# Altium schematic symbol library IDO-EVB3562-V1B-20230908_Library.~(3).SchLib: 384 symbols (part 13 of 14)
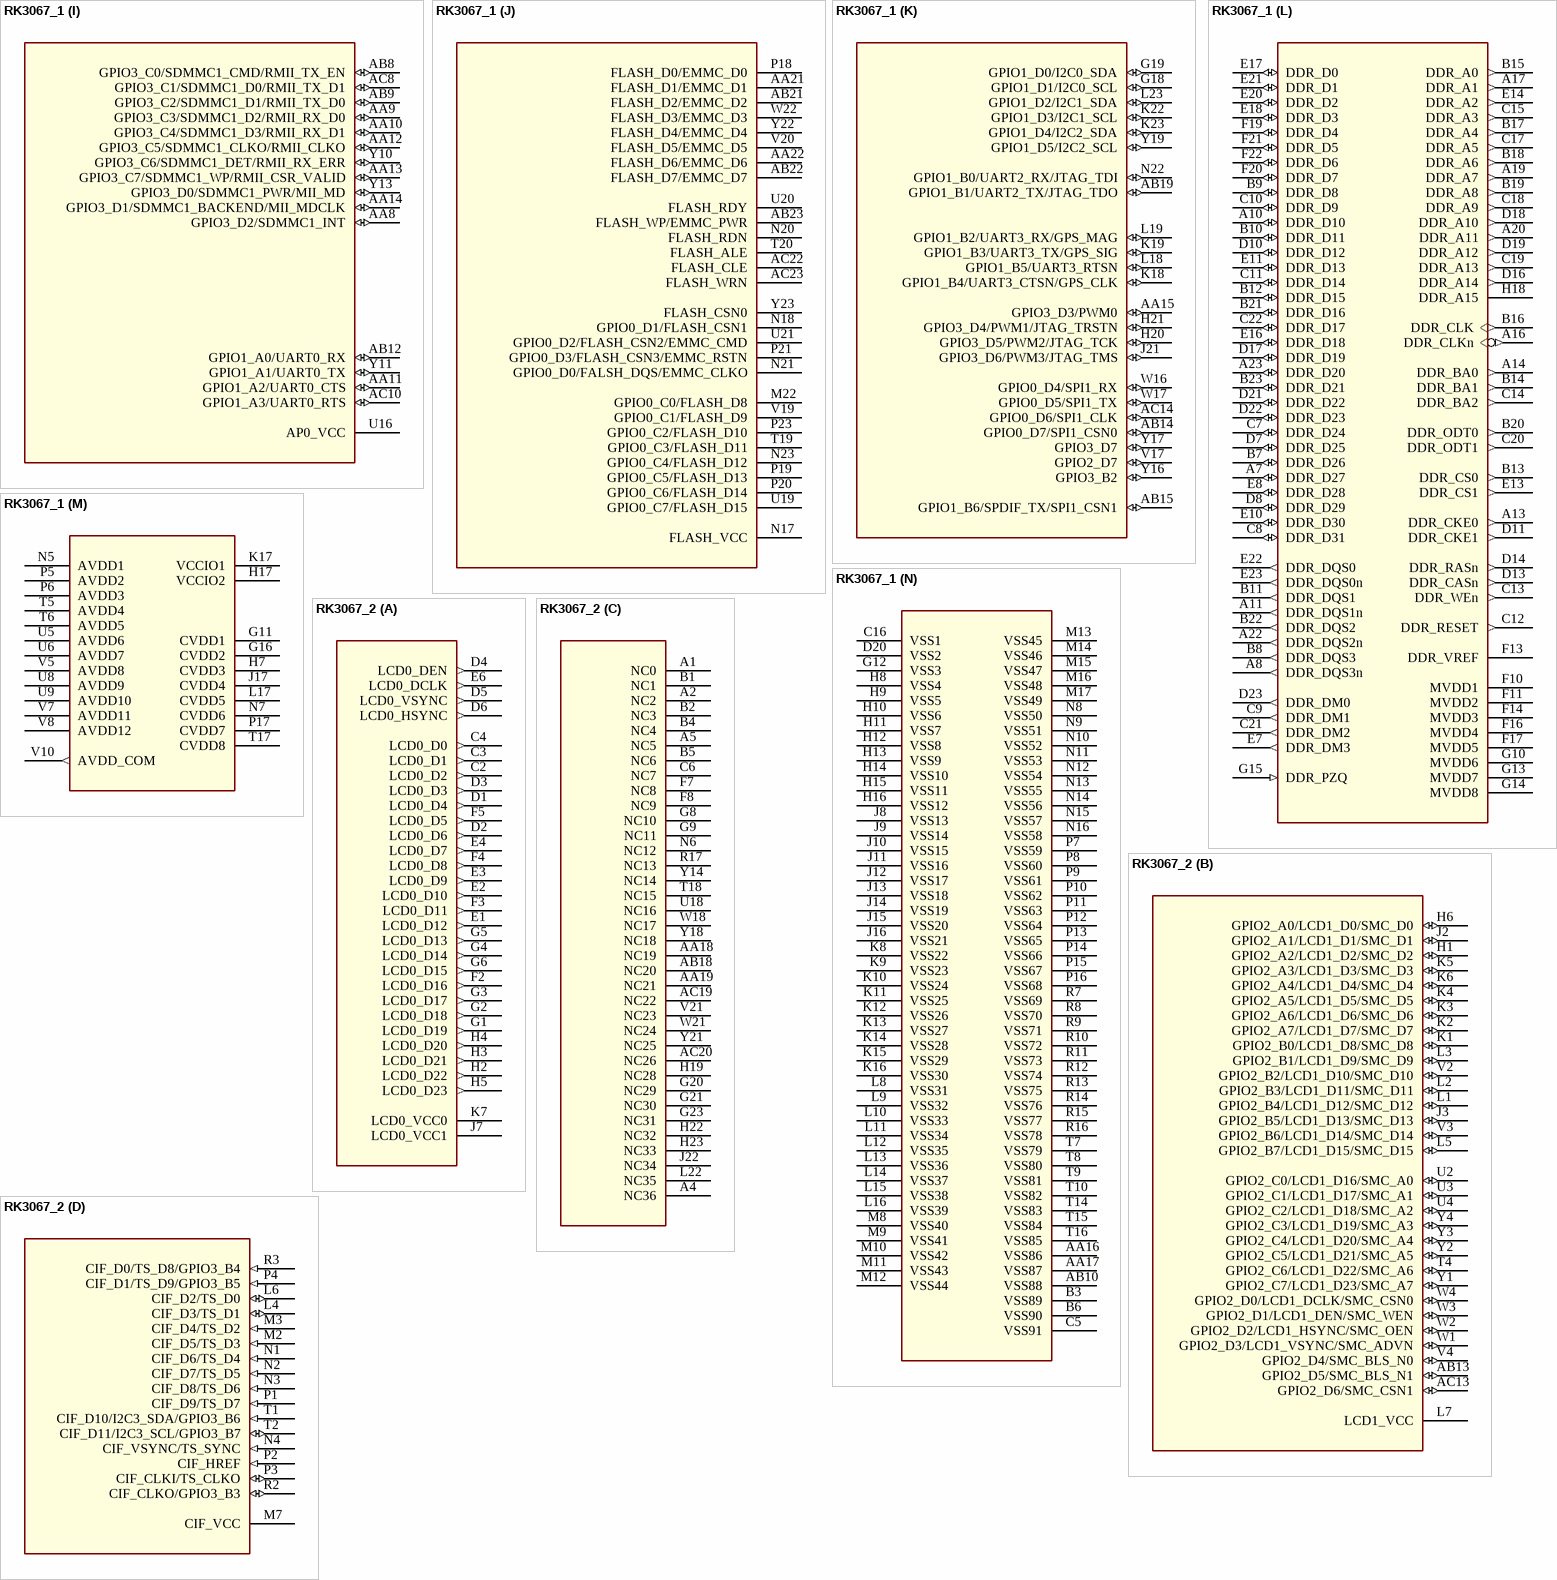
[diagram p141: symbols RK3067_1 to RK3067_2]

## RK3067_1
designator U?
Altium-Right: 70; Altium-Bottom: 390; Altium-Right1: 150; Altium-Bottom1: 210; Altium-Bottom2: 250; Altium-Right3: 230; Altium-Bottom3: 180; Altium-Bottom4: 240; Altium-Right5: 160; Altium-Bottom5: 130; Altium-Right6: 220; Altium-Bottom6: 280; Altium-Right7: 200; Altium-Bottom7: 350; Altium-Bottom8: 330; Altium-Right9: 140; Altium-Bottom9: 520; Altium-Right10: 110; Altium-Bottom10: 170; Altium-Right11: 100; Altium-Bottom11: 500; Altium-Right12: 80; Altium-Bottom13: 370
footprint BGA453-19X19
part A pins: C2 LCD0_D2 (out), C3 LCD0_D1 (out), C4 LCD0_D0 (out), D1 LCD0_D4 (out), D2 LCD0_D6 (out), D3 LCD0_D3 (out), D4 LCD0_DEN (out), D5 LCD0_VSYNC (out), D6 LCD0_HSYNC (out), E1 LCD0_D12 (out), E2 LCD0_D10 (out), E3 LCD0_D9 (out), E4 LCD0_D7 (out), E6 LCD0_DCLK (out), F2 LCD0_D16 (out), F3 LCD0_D11 (out), F4 LCD0_D8 (out), F5 LCD0_D5 (out), G1 LCD0_D19 (out), G2 LCD0_D18 (out), G3 LCD0_D17 (out), G4 LCD0_D14 (out), G5 LCD0_D13 (out), G6 LCD0_D15 (out), H2 LCD0_D22 (out), H3 LCD0_D21 (out), H4 LCD0_D20 (out), H5 LCD0_D23 (out), J7 LCD0_VCC1 (power), K7 LCD0_VCC0 (power)
part B pins: AB13 GPIO2_D5/SMC_BLS_N1 (io), AC13 GPIO2_D6/SMC_CSN1 (io), H1 GPIO2_A2/LCD1_D2/SMC_D2 (io), H6 GPIO2_A0/LCD1_D0/SMC_D0 (io), J2 GPIO2_A1/LCD1_D1/SMC_D1 (io), J3 GPIO2_B5/LCD1_D13/SMC_D13 (io), K1 GPIO2_B0/LCD1_D8/SMC_D8 (io), K2 GPIO2_A7/LCD1_D7/SMC_D7 (io), K3 GPIO2_A6/LCD1_D6/SMC_D6 (io), K4 GPIO2_A5/LCD1_D5/SMC_D5 (io), K5 GPIO2_A3/LCD1_D3/SMC_D3 (io), K6 GPIO2_A4/LCD1_D4/SMC_D4 (io), L1 GPIO2_B4/LCD1_D12/SMC_D12 (io), L2 GPIO2_B3/LCD1_D11/SMC_D11 (io), L3 GPIO2_B1/LCD1_D9/SMC_D9 (io), L5 GPIO2_B7/LCD1_D15/SMC_D15 (io), L7 LCD1_VCC (power), T4 GPIO2_C6/LCD1_D22/SMC_A6 (io), U2 GPIO2_C0/LCD1_D16/SMC_A0 (io), U3 GPIO2_C1/LCD1_D17/SMC_A1 (io), U4 GPIO2_C2/LCD1_D18/SMC_A2 (io), V2 GPIO2_B2/LCD1_D10/SMC_D10 (io), V3 GPIO2_B6/LCD1_D14/SMC_D14 (io), V4 GPIO2_D4/SMC_BLS_N0 (io), W1 GPIO2_D3/LCD1_VSYNC/SMC_ADVN (io), W2 GPIO2_D2/LCD1_HSYNC/SMC_OEN (io), W3 GPIO2_D1/LCD1_DEN/SMC_WEN (io), W4 GPIO2_D0/LCD1_DCLK/SMC_CSN0 (io), Y1 GPIO2_C7/LCD1_D23/SMC_A7 (io), Y2 GPIO2_C5/LCD1_D21/SMC_A5 (io), Y3 GPIO2_C4/LCD1_D20/SMC_A4 (io), Y4 GPIO2_C3/LCD1_D19/SMC_A3 (io)
part C pins: A1 NC0, A2 NC2, A4 NC36, A5 NC5, AA18 NC19, AA19 NC21, AB18 NC20, AC19 NC22, AC20 NC26, B1 NC1, B2 NC3, B4 NC4, B5 NC6, C6 NC7, F7 NC8, F8 NC9, G8 NC10, G9 NC11, G20 NC29, G21 NC30, G23 NC31, H19 NC28, H22 NC32, H23 NC33, J22 NC34, L22 NC35, N6 NC12, R17 NC13, T18 NC15, U18 NC16, V21 NC23, W18 NC17, W21 NC24, Y14 NC14, Y18 NC18, Y21 NC25
part D pins: L4 CIF_D3/TS_D1 (io), L6 CIF_D2/TS_D0 (io), M2 CIF_D5/TS_D3 (in), M3 CIF_D4/TS_D2 (in), M7 CIF_VCC (power), N1 CIF_D6/TS_D4 (in), N2 CIF_D7/TS_D5 (in), N3 CIF_D8/TS_D6 (in), N4 CIF_VSYNC/TS_SYNC (in), P1 CIF_D9/TS_D7 (in), P2 CIF_HREF (in), P3 CIF_CLKI/TS_CLKO (io), P4 CIF_D1/TS_D9/GPIO3_B5 (in), R2 CIF_CLKO/GPIO3_B3 (io), R3 CIF_D0/TS_D8/GPIO3_B4 (in), T1 CIF_D10/I2C3_SDA/GPIO3_B6 (in), T2 CIF_D11/I2C3_SCL/GPIO3_B7 (io)
part E pins: AA2 GPIO0_A0, AA3 GPIO0_A3, AA4 CLKIN_32K (in), AA5 GPIO0_A7, AB1 CPU_PWROFF (out), AB2 GPIO0_A1, AB3 GPIO0_A4, AB11 XOUT24M (out), AC1 CORE_PWROFF (out), AC2 GPIO0_A2, AC4 GPIO0_A5, AC11 XIN24M (in), T11 AVSS_APLL (power), T12 AVSS_C/GPLL (power), T13 AVSS_DPLL (power), U10 APLL_1V0 (power), U11 C/GPLL_1V0 (power), U12 DPLL_1V0 (power), U13 PVDD_1V0 (power), V13 PVCC_3V3 (power), W10 GPIO0_B0, W11 GPIO0_B1, W14 EFUSE (in), Y5 GPIO0_B3, Y6 GPIO0_B2, Y7 NPOR (in), Y8 GPIO0_A6
part F pins: AA6 OTG_RKELVIN (out), AB4 OTG_ID (in), AB5 OTG_VBUS (in), AB16 OTG_DM (io), AB17 HOST_DM (io), AC16 OTG_DP (io), AC17 HOST_DP (io), G22 JTAG_SEL (in), U14 USBVDD_1V0 (power), U15 USBVDD_1V8 (power), V11 ADCVDD_1V8 (power), V14 USBVDD_3V3 (power), W6 SARADC_ANI0 (in), W7 SARADC_ANI2 (in), W8 SARADC_ANI1 (in), W13 HOST_RKELVIN (out)
part G pins: AA7 GPIO1_A4/UART1_RX (io), AA20 GPIO0_B6 (io), AB6 GPIO1_A6/UART1_CTSN (io), AB7 GPIO1_A7/UART1_RTSN (io), AB20 GPIO0_B7 (io), AC5 GPIO1_A5/UART1_TX (io), AC7 GPIO1_B7/SPI0_CSN1 (io), K21 GPIO1_C5/I2S_SDO (io), L21 GPIO1_C4/I2S_SDI (io), R21 GPIO1_C3/I2S_LRCK_TX (io), R22 GPIO1_C2/I2S_LRCK_RX (io), T3 GPIO1_D6/I2C4_SDA (io), T22 GPIO1_C0/I2S_CLK (io), T23 GPIO1_C1/I2S_SCLK (io), U1 GPIO1_D7/I2C4_SCL (io), V16 AP1_VCC (power), W20 GPIO0_B4 (io), Y20 GPIO0_B5 (io)
part H pins: K20 GPIO3_A7/SDMMC0_D3 (io), L20 GPIO3_B0/SDMMC0_DET (io), M21 GPIO3_A4/SDMMC0_D0 (io), N19 GPIO3_B1/SDMMC0_WP (io), P22 GPIO3_A3/SDMMC0_CMD (io), T21 GPIO3_A6/SDMMC0_D2 (io), U22 GPIO3_A2/SDMMC0_CLKO (io), U23 GPIO3_A5/SDMMC0_D1 (io), V22 GPIO3_A1/SDMMC0_PWR (io), W23 GPIO3_A0/SDMMC0_RSTN (io)
part I pins: AA8 GPIO3_D2/SDMMC1_INT (io), AA9 GPIO3_C3/SDMMC1_D2/RMII_RX_D0 (io), AA10 GPIO3_C4/SDMMC1_D3/RMII_RX_D1 (io), AA11 GPIO1_A2/UART0_CTS (io), AA12 GPIO3_C5/SDMMC1_CLKO/RMII_CLKO (io), AA13 GPIO3_C7/SDMMC1_WP/RMII_CSR_VALID (io), AA14 GPIO3_D1/SDMMC1_BACKEND/MII_MDCLK (io), AB8 GPIO3_C0/SDMMC1_CMD/RMII_TX_EN (io), AB9 GPIO3_C2/SDMMC1_D1/RMII_TX_D0 (io), AB12 GPIO1_A0/UART0_RX (io), AC8 GPIO3_C1/SDMMC1_D0/RMII_TX_D1 (io), AC10 GPIO1_A3/UART0_RTS (io), U16 AP0_VCC (power), Y10 GPIO3_C6/SDMMC1_DET/RMII_RX_ERR (io), Y11 GPIO1_A1/UART0_TX (io), Y13 GPIO3_D0/SDMMC1_PWR/MII_MD (io)
part J pins: AA21 FLASH_D1/EMMC_D1, AA22 FLASH_D6/EMMC_D6, AB21 FLASH_D2/EMMC_D2, AB22 FLASH_D7/EMMC_D7, AB23 FLASH_WP/EMMC_PWR, AC22 FLASH_CLE, AC23 FLASH_WRN, M22 GPIO0_C0/FLASH_D8, N17 FLASH_VCC, N18 GPIO0_D1/FLASH_CSN1, N20 FLASH_RDN, N21 GPIO0_D0/FALSH_DQS/EMMC_CLKO, N23 GPIO0_C4/FLASH_D12, P18 FLASH_D0/EMMC_D0, P19 GPIO0_C5/FLASH_D13, P20 GPIO0_C6/FLASH_D14, P21 GPIO0_D3/FLASH_CSN3/EMMC_RSTN, P23 GPIO0_C2/FLASH_D10, T19 GPIO0_C3/FLASH_D11, T20 FLASH_ALE, U19 GPIO0_C7/FLASH_D15, U20 FLASH_RDY, U21 GPIO0_D2/FLASH_CSN2/EMMC_CMD, V19 GPIO0_C1/FLASH_D9, V20 FLASH_D5/EMMC_D5, W22 FLASH_D3/EMMC_D3, Y22 FLASH_D4/EMMC_D4, Y23 FLASH_CSN0
part K pins: AA15 GPIO3_D3/PWM0 (io), AB14 GPIO0_D7/SPI1_CSN0 (io), AB15 GPIO1_B6/SPDIF_TX/SPI1_CSN1 (io), AB19 GPIO1_B1/UART2_TX/JTAG_TDO (io), AC14 GPIO0_D6/SPI1_CLK (io), G18 GPIO1_D1/I2C0_SCL (io), G19 GPIO1_D0/I2C0_SDA (io), H20 GPIO3_D5/PWM2/JTAG_TCK (io), H21 GPIO3_D4/PWM1/JTAG_TRSTN (io), J21 GPIO3_D6/PWM3/JTAG_TMS (io), K18 GPIO1_B4/UART3_CTSN/GPS_CLK (io), K19 GPIO1_B3/UART3_TX/GPS_SIG (io), K22 GPIO1_D3/I2C1_SCL (io), K23 GPIO1_D4/I2C2_SDA (io), L18 GPIO1_B5/UART3_RTSN (io), L19 GPIO1_B2/UART3_RX/GPS_MAG (io), L23 GPIO1_D2/I2C1_SDA (io), N22 GPIO1_B0/UART2_RX/JTAG_TDI (io), V17 GPIO2_D7 (io), W16 GPIO0_D4/SPI1_RX (io), W17 GPIO0_D5/SPI1_TX (io), Y16 GPIO3_B2 (io), Y17 GPIO3_D7 (io), Y19 GPIO1_D5/I2C2_SCL (io)
part L pins: A7 DDR_D27 (io), A8 DDR_DQS3n (out), A10 DDR_D10 (io), A11 DDR_DQS1n (out), A13 DDR_CKE0 (out), A14 DDR_BA0 (out), A16 DDR_CLKn (out), A17 DDR_A1 (out), A19 DDR_A7 (out), A20 DDR_A11 (out), A22 DDR_DQS2n (out), A23 DDR_D20 (io), B7 DDR_D26 (io), B8 DDR_DQS3 (out), B9 DDR_D8 (io), B10 DDR_D11 (io), B11 DDR_DQS1 (out), B12 DDR_D15 (io), B13 DDR_CS0 (out), B14 DDR_BA1 (out), B15 DDR_A0 (out), B16 DDR_CLK (out), B17 DDR_A4 (out), B18 DDR_A6 (out), B19 DDR_A8 (out), B20 DDR_ODT0 (out), B21 DDR_D16 (io), B22 DDR_DQS2 (out), B23 DDR_D21 (io), C7 DDR_D24 (io), C8 DDR_D31 (io), C9 DDR_DM1 (out), C10 DDR_D9 (io), C11 DDR_D14 (io), C12 DDR_RESET (out), C13 DDR_WEn (out), C14 DDR_BA2 (out), C15 DDR_A3 (out), C17 DDR_A5 (out), C18 DDR_A9 (out), C19 DDR_A13 (out), C20 DDR_ODT1 (out), C21 DDR_DM2 (out), C22 DDR_D17 (io), D7 DDR_D25 (io), D8 DDR_D29 (io), D10 DDR_D12 (io), D11 DDR_CKE1 (out), D13 DDR_CASn (out), D14 DDR_RASn (out), D16 DDR_A14 (out), D17 DDR_D19 (io), D18 DDR_A10 (out), D19 DDR_A12 (out), D21 DDR_D22 (io), D22 DDR_D23 (io), D23 DDR_DM0 (out), E7 DDR_DM3 (out), E8 DDR_D28 (io), E10 DDR_D30 (io), E11 DDR_D13 (io), E13 DDR_CS1 (out), E14 DDR_A2 (out), E16 DDR_D18 (io), E17 DDR_D0 (io), E18 DDR_D3 (io), E20 DDR_D2 (io), E21 DDR_D1 (io), E22 DDR_DQS0 (out), E23 DDR_DQS0n (out), F10 MVDD1 (power), F11 MVDD2 (power), F13 DDR_VREF (power), F14 MVDD3 (power), F16 MVDD4 (power), F17 MVDD5 (power), F19 DDR_D4 (io), F20 DDR_D7 (io), F21 DDR_D5 (io), F22 DDR_D6 (io), G10 MVDD6 (power), G13 MVDD7 (power), G14 MVDD8 (power), G15 DDR_PZQ (in), H18 DDR_A15
part M pins: G11 CVDD1 (power), G16 CVDD2 (power), H7 CVDD3 (power), H17 VCCIO2 (power), J17 CVDD4 (power), K17 VCCIO1 (power), L17 CVDD5 (power), N5 AVDD1 (power), N7 CVDD6 (power), P5 AVDD2 (power), P6 AVDD3 (power), P17 CVDD7 (power), T5 AVDD4 (power), T6 AVDD5 (power), T17 CVDD8 (power), U5 AVDD6 (power), U6 AVDD7 (power), U8 AVDD9 (power), U9 AVDD10 (power), V5 AVDD8 (power), V7 AVDD11 (power), V8 AVDD12 (power), V10 AVDD_COM (out)
part N pins: AA16 VSS86 (power), AA17 VSS87 (power), AB10 VSS88 (power), B3 VSS89 (power), B6 VSS90 (power), C5 VSS91 (power), C16 VSS1 (power), D20 VSS2 (power), G12 VSS3 (power), H8 VSS4 (power), H9 VSS5 (power), H10 VSS6 (power), H11 VSS7 (power), H12 VSS8 (power), H13 VSS9 (power), H14 VSS10 (power), H15 VSS11 (power), H16 VSS12 (power), J8 VSS13 (power), J9 VSS14 (power), J10 VSS15 (power), J11 VSS16 (power), J12 VSS17 (power), J13 VSS18 (power), J14 VSS19 (power), J15 VSS20 (power), J16 VSS21 (power), K8 VSS22 (power), K9 VSS23 (power), K10 VSS24 (power), K11 VSS25 (power), K12 VSS26 (power), K13 VSS27 (power), K14 VSS28 (power), K15 VSS29 (power), K16 VSS30 (power), L8 VSS31 (power), L9 VSS32 (power), L10 VSS33 (power), L11 VSS34 (power), L12 VSS35 (power), L13 VSS36 (power), L14 VSS37 (power), L15 VSS38 (power), L16 VSS39 (power), M8 VSS40 (power), M9 VSS41 (power), M10 VSS42 (power), M11 VSS43 (power), M12 VSS44 (power), M13 VSS45 (power), M14 VSS46 (power), M15 VSS47 (power), M16 VSS48 (power), M17 VSS49 (power), N8 VSS50 (power), N9 VSS51 (power), N10 VSS52 (power), N11 VSS53 (power), N12 VSS54 (power), N13 VSS55 (power), N14 VSS56 (power), N15 VSS57 (power), N16 VSS58 (power), P7 VSS59 (power), P8 VSS60 (power), P9 VSS61 (power), P10 VSS62 (power), P11 VSS63 (power), P12 VSS64 (power), P13 VSS65 (power), P14 VSS66 (power), P15 VSS67 (power), P16 VSS68 (power), R7 VSS69 (power), R8 VSS70 (power), R9 VSS71 (power), R10 VSS72 (power), R11 VSS73 (power), R12 VSS74 (power), R13 VSS75 (power), R14 VSS76 (power), R15 VSS77 (power), R16 VSS78 (power), T7 VSS79 (power), T8 VSS80 (power), T9 VSS81 (power), T10 VSS82 (power), T14 VSS83 (power), T15 VSS84 (power), T16 VSS85 (power)

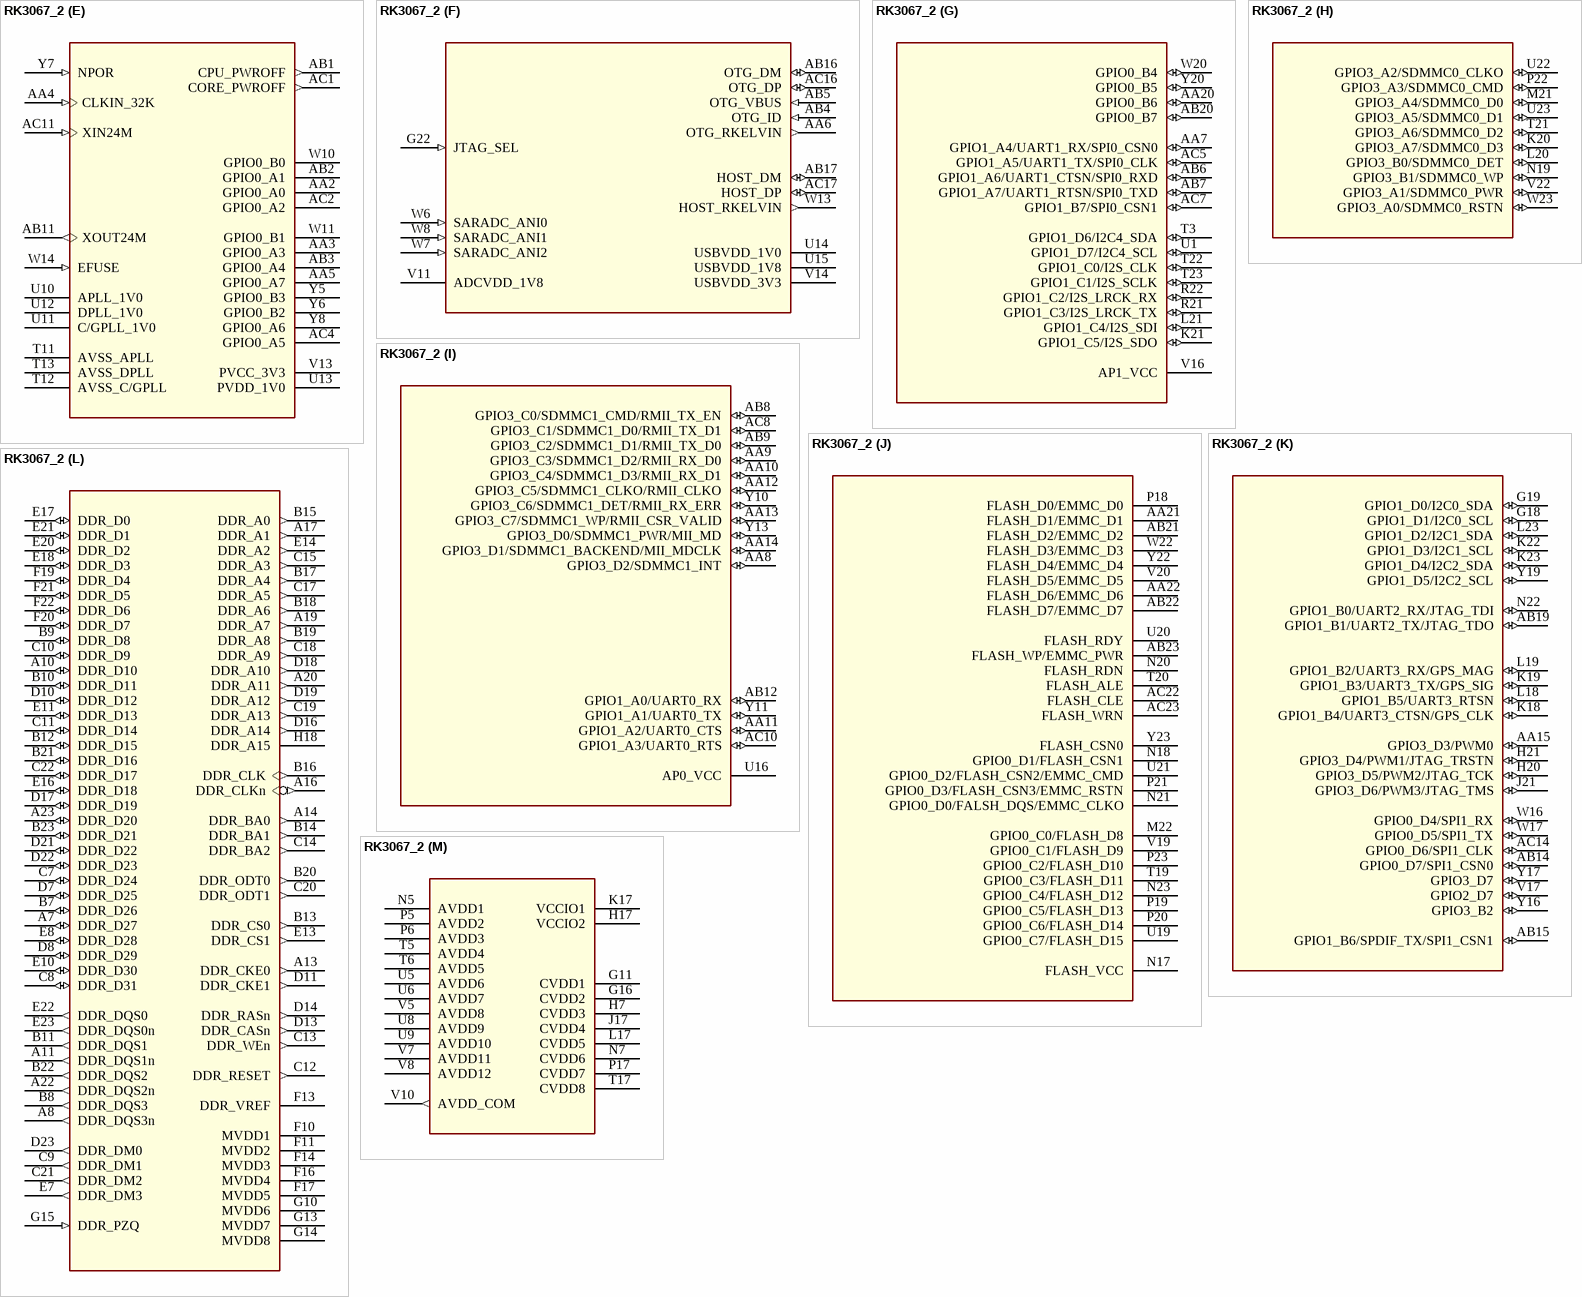
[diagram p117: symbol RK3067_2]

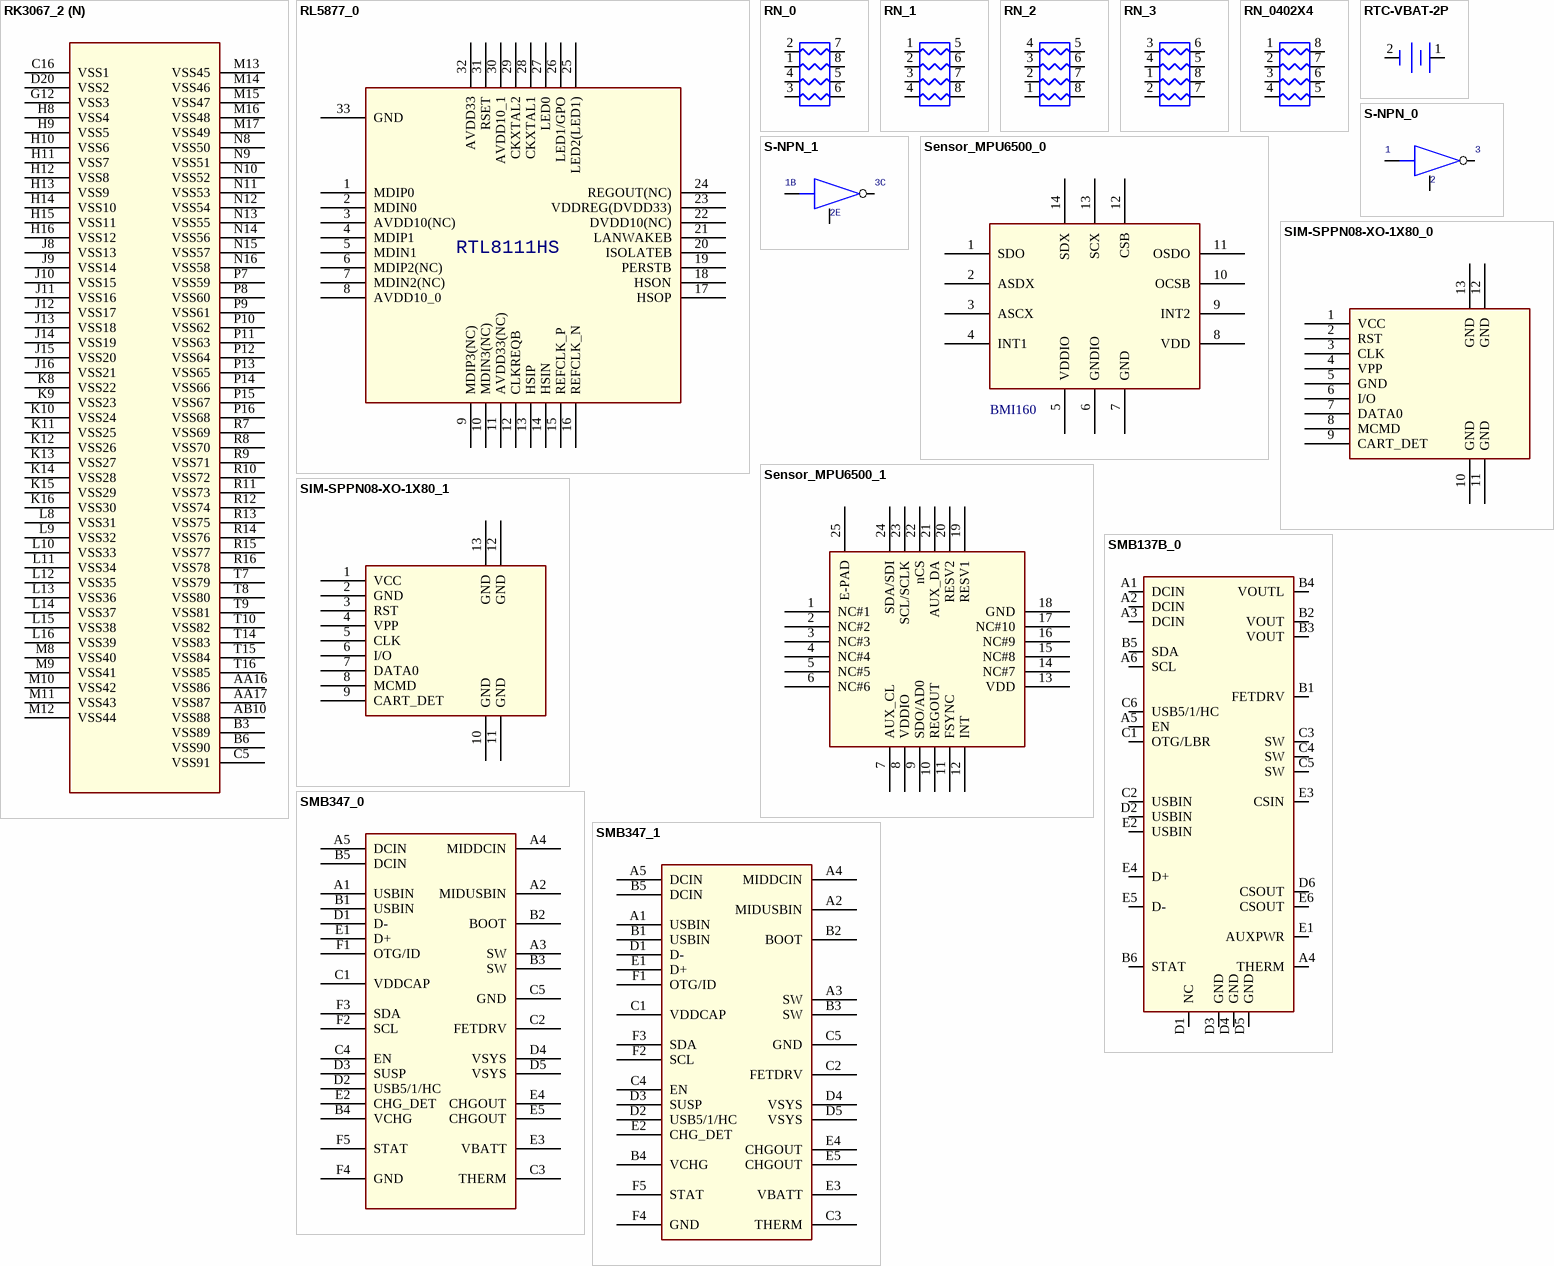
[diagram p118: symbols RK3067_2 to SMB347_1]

## RK3067_2
designator U?
Altium-Right: 150; Altium-Bottom: 210; Altium-Bottom1: 250; Altium-Right2: 230; Altium-Bottom2: 180; Altium-Bottom3: 240; Altium-Right4: 160; Altium-Bottom4: 130; Altium-Right5: 220; Altium-Bottom5: 280; Altium-Right6: 200; Altium-Bottom6: 350; Altium-Bottom7: 330; Altium-Right8: 140; Altium-Bottom8: 520; Altium-Right9: 110; Altium-Bottom9: 170; Altium-Right10: 100; Altium-Bottom10: 500; Altium-Right11: 80; Altium-Bottom12: 370; Altium-Right13: 70; Altium-Bottom13: 390
footprint BGA453-19X19
part A pins: C2 LCD0_D2 (out), C3 LCD0_D1 (out), C4 LCD0_D0 (out), D1 LCD0_D4 (out), D2 LCD0_D6 (out), D3 LCD0_D3 (out), D4 LCD0_DEN (out), D5 LCD0_VSYNC (out), D6 LCD0_HSYNC (out), E1 LCD0_D12 (out), E2 LCD0_D10 (out), E3 LCD0_D9 (out), E4 LCD0_D7 (out), E6 LCD0_DCLK (out), F2 LCD0_D16 (out), F3 LCD0_D11 (out), F4 LCD0_D8 (out), F5 LCD0_D5 (out), G1 LCD0_D19 (out), G2 LCD0_D18 (out), G3 LCD0_D17 (out), G4 LCD0_D14 (out), G5 LCD0_D13 (out), G6 LCD0_D15 (out), H2 LCD0_D22 (out), H3 LCD0_D21 (out), H4 LCD0_D20 (out), H5 LCD0_D23 (out), J7 LCD0_VCC1 (power), K7 LCD0_VCC0 (power)
part B pins: AB13 GPIO2_D5/SMC_BLS_N1 (io), AC13 GPIO2_D6/SMC_CSN1 (io), H1 GPIO2_A2/LCD1_D2/SMC_D2 (io), H6 GPIO2_A0/LCD1_D0/SMC_D0 (io), J2 GPIO2_A1/LCD1_D1/SMC_D1 (io), J3 GPIO2_B5/LCD1_D13/SMC_D13 (io), K1 GPIO2_B0/LCD1_D8/SMC_D8 (io), K2 GPIO2_A7/LCD1_D7/SMC_D7 (io), K3 GPIO2_A6/LCD1_D6/SMC_D6 (io), K4 GPIO2_A5/LCD1_D5/SMC_D5 (io), K5 GPIO2_A3/LCD1_D3/SMC_D3 (io), K6 GPIO2_A4/LCD1_D4/SMC_D4 (io), L1 GPIO2_B4/LCD1_D12/SMC_D12 (io), L2 GPIO2_B3/LCD1_D11/SMC_D11 (io), L3 GPIO2_B1/LCD1_D9/SMC_D9 (io), L5 GPIO2_B7/LCD1_D15/SMC_D15 (io), L7 LCD1_VCC (power), T4 GPIO2_C6/LCD1_D22/SMC_A6 (io), U2 GPIO2_C0/LCD1_D16/SMC_A0 (io), U3 GPIO2_C1/LCD1_D17/SMC_A1 (io), U4 GPIO2_C2/LCD1_D18/SMC_A2 (io), V2 GPIO2_B2/LCD1_D10/SMC_D10 (io), V3 GPIO2_B6/LCD1_D14/SMC_D14 (io), V4 GPIO2_D4/SMC_BLS_N0 (io), W1 GPIO2_D3/LCD1_VSYNC/SMC_ADVN (io), W2 GPIO2_D2/LCD1_HSYNC/SMC_OEN (io), W3 GPIO2_D1/LCD1_DEN/SMC_WEN (io), W4 GPIO2_D0/LCD1_DCLK/SMC_CSN0 (io), Y1 GPIO2_C7/LCD1_D23/SMC_A7 (io), Y2 GPIO2_C5/LCD1_D21/SMC_A5 (io), Y3 GPIO2_C4/LCD1_D20/SMC_A4 (io), Y4 GPIO2_C3/LCD1_D19/SMC_A3 (io)
part C pins: A1 NC0, A2 NC2, A4 NC36, A5 NC5, AA18 NC19, AA19 NC21, AB18 NC20, AC19 NC22, AC20 NC26, B1 NC1, B2 NC3, B4 NC4, B5 NC6, C6 NC7, F7 NC8, F8 NC9, G8 NC10, G9 NC11, G20 NC29, G21 NC30, G23 NC31, H19 NC28, H22 NC32, H23 NC33, J22 NC34, L22 NC35, N6 NC12, R17 NC13, T18 NC15, U18 NC16, V21 NC23, W18 NC17, W21 NC24, Y14 NC14, Y18 NC18, Y21 NC25
part D pins: L4 CIF_D3/TS_D1 (io), L6 CIF_D2/TS_D0 (io), M2 CIF_D5/TS_D3 (in), M3 CIF_D4/TS_D2 (in), M7 CIF_VCC (power), N1 CIF_D6/TS_D4 (in), N2 CIF_D7/TS_D5 (in), N3 CIF_D8/TS_D6 (in), N4 CIF_VSYNC/TS_SYNC (in), P1 CIF_D9/TS_D7 (in), P2 CIF_HREF (in), P3 CIF_CLKI/TS_CLKO (io), P4 CIF_D1/TS_D9/GPIO3_B5 (in), R2 CIF_CLKO/GPIO3_B3 (io), R3 CIF_D0/TS_D8/GPIO3_B4 (in), T1 CIF_D10/I2C3_SDA/GPIO3_B6 (in), T2 CIF_D11/I2C3_SCL/GPIO3_B7 (io)
part E pins: AA2 GPIO0_A0, AA3 GPIO0_A3, AA4 CLKIN_32K (in), AA5 GPIO0_A7, AB1 CPU_PWROFF (out), AB2 GPIO0_A1, AB3 GPIO0_A4, AB11 XOUT24M (out), AC1 CORE_PWROFF (out), AC2 GPIO0_A2, AC4 GPIO0_A5, AC11 XIN24M (in), T11 AVSS_APLL (power), T12 AVSS_C/GPLL (power), T13 AVSS_DPLL (power), U10 APLL_1V0 (power), U11 C/GPLL_1V0 (power), U12 DPLL_1V0 (power), U13 PVDD_1V0 (power), V13 PVCC_3V3 (power), W10 GPIO0_B0, W11 GPIO0_B1, W14 EFUSE (in), Y5 GPIO0_B3, Y6 GPIO0_B2, Y7 NPOR (in), Y8 GPIO0_A6
part F pins: AA6 OTG_RKELVIN (out), AB4 OTG_ID (in), AB5 OTG_VBUS (in), AB16 OTG_DM (io), AB17 HOST_DM (io), AC16 OTG_DP (io), AC17 HOST_DP (io), G22 JTAG_SEL (in), U14 USBVDD_1V0 (power), U15 USBVDD_1V8 (power), V11 ADCVDD_1V8 (power), V14 USBVDD_3V3 (power), W6 SARADC_ANI0 (in), W7 SARADC_ANI2 (in), W8 SARADC_ANI1 (in), W13 HOST_RKELVIN (out)
part G pins: AA7 GPIO1_A4/UART1_RX/SPI0_CSN0 (io), AA20 GPIO0_B6 (io), AB6 GPIO1_A6/UART1_CTSN/SPI0_RXD (io), AB7 GPIO1_A7/UART1_RTSN/SPI0_TXD (io), AB20 GPIO0_B7 (io), AC5 GPIO1_A5/UART1_TX/SPI0_CLK (io), AC7 GPIO1_B7/SPI0_CSN1 (io), K21 GPIO1_C5/I2S_SDO (io), L21 GPIO1_C4/I2S_SDI (io), R21 GPIO1_C3/I2S_LRCK_TX (io), R22 GPIO1_C2/I2S_LRCK_RX (io), T3 GPIO1_D6/I2C4_SDA (io), T22 GPIO1_C0/I2S_CLK (io), T23 GPIO1_C1/I2S_SCLK (io), U1 GPIO1_D7/I2C4_SCL (io), V16 AP1_VCC (power), W20 GPIO0_B4 (io), Y20 GPIO0_B5 (io)
part H pins: K20 GPIO3_A7/SDMMC0_D3 (io), L20 GPIO3_B0/SDMMC0_DET (io), M21 GPIO3_A4/SDMMC0_D0 (io), N19 GPIO3_B1/SDMMC0_WP (io), P22 GPIO3_A3/SDMMC0_CMD (io), T21 GPIO3_A6/SDMMC0_D2 (io), U22 GPIO3_A2/SDMMC0_CLKO (io), U23 GPIO3_A5/SDMMC0_D1 (io), V22 GPIO3_A1/SDMMC0_PWR (io), W23 GPIO3_A0/SDMMC0_RSTN (io)
part I pins: AA8 GPIO3_D2/SDMMC1_INT (io), AA9 GPIO3_C3/SDMMC1_D2/RMII_RX_D0 (io), AA10 GPIO3_C4/SDMMC1_D3/RMII_RX_D1 (io), AA11 GPIO1_A2/UART0_CTS (io), AA12 GPIO3_C5/SDMMC1_CLKO/RMII_CLKO (io), AA13 GPIO3_C7/SDMMC1_WP/RMII_CSR_VALID (io), AA14 GPIO3_D1/SDMMC1_BACKEND/MII_MDCLK (io), AB8 GPIO3_C0/SDMMC1_CMD/RMII_TX_EN (io), AB9 GPIO3_C2/SDMMC1_D1/RMII_TX_D0 (io), AB12 GPIO1_A0/UART0_RX (io), AC8 GPIO3_C1/SDMMC1_D0/RMII_TX_D1 (io), AC10 GPIO1_A3/UART0_RTS (io), U16 AP0_VCC (power), Y10 GPIO3_C6/SDMMC1_DET/RMII_RX_ERR (io), Y11 GPIO1_A1/UART0_TX (io), Y13 GPIO3_D0/SDMMC1_PWR/MII_MD (io)
part J pins: AA21 FLASH_D1/EMMC_D1, AA22 FLASH_D6/EMMC_D6, AB21 FLASH_D2/EMMC_D2, AB22 FLASH_D7/EMMC_D7, AB23 FLASH_WP/EMMC_PWR, AC22 FLASH_CLE, AC23 FLASH_WRN, M22 GPIO0_C0/FLASH_D8, N17 FLASH_VCC, N18 GPIO0_D1/FLASH_CSN1, N20 FLASH_RDN, N21 GPIO0_D0/FALSH_DQS/EMMC_CLKO, N23 GPIO0_C4/FLASH_D12, P18 FLASH_D0/EMMC_D0, P19 GPIO0_C5/FLASH_D13, P20 GPIO0_C6/FLASH_D14, P21 GPIO0_D3/FLASH_CSN3/EMMC_RSTN, P23 GPIO0_C2/FLASH_D10, T19 GPIO0_C3/FLASH_D11, T20 FLASH_ALE, U19 GPIO0_C7/FLASH_D15, U20 FLASH_RDY, U21 GPIO0_D2/FLASH_CSN2/EMMC_CMD, V19 GPIO0_C1/FLASH_D9, V20 FLASH_D5/EMMC_D5, W22 FLASH_D3/EMMC_D3, Y22 FLASH_D4/EMMC_D4, Y23 FLASH_CSN0
part K pins: AA15 GPIO3_D3/PWM0 (io), AB14 GPIO0_D7/SPI1_CSN0 (io), AB15 GPIO1_B6/SPDIF_TX/SPI1_CSN1 (io), AB19 GPIO1_B1/UART2_TX/JTAG_TDO (io), AC14 GPIO0_D6/SPI1_CLK (io), G18 GPIO1_D1/I2C0_SCL (io), G19 GPIO1_D0/I2C0_SDA (io), H20 GPIO3_D5/PWM2/JTAG_TCK (io), H21 GPIO3_D4/PWM1/JTAG_TRSTN (io), J21 GPIO3_D6/PWM3/JTAG_TMS (io), K18 GPIO1_B4/UART3_CTSN/GPS_CLK (io), K19 GPIO1_B3/UART3_TX/GPS_SIG (io), K22 GPIO1_D3/I2C1_SCL (io), K23 GPIO1_D4/I2C2_SDA (io), L18 GPIO1_B5/UART3_RTSN (io), L19 GPIO1_B2/UART3_RX/GPS_MAG (io), L23 GPIO1_D2/I2C1_SDA (io), N22 GPIO1_B0/UART2_RX/JTAG_TDI (io), V17 GPIO2_D7 (io), W16 GPIO0_D4/SPI1_RX (io), W17 GPIO0_D5/SPI1_TX (io), Y16 GPIO3_B2 (io), Y17 GPIO3_D7 (io), Y19 GPIO1_D5/I2C2_SCL (io)
part L pins: A7 DDR_D27 (io), A8 DDR_DQS3n (out), A10 DDR_D10 (io), A11 DDR_DQS1n (out), A13 DDR_CKE0 (out), A14 DDR_BA0 (out), A16 DDR_CLKn (out), A17 DDR_A1 (out), A19 DDR_A7 (out), A20 DDR_A11 (out), A22 DDR_DQS2n (out), A23 DDR_D20 (io), B7 DDR_D26 (io), B8 DDR_DQS3 (out), B9 DDR_D8 (io), B10 DDR_D11 (io), B11 DDR_DQS1 (out), B12 DDR_D15 (io), B13 DDR_CS0 (out), B14 DDR_BA1 (out), B15 DDR_A0 (out), B16 DDR_CLK (out), B17 DDR_A4 (out), B18 DDR_A6 (out), B19 DDR_A8 (out), B20 DDR_ODT0 (out), B21 DDR_D16 (io), B22 DDR_DQS2 (out), B23 DDR_D21 (io), C7 DDR_D24 (io), C8 DDR_D31 (io), C9 DDR_DM1 (out), C10 DDR_D9 (io), C11 DDR_D14 (io), C12 DDR_RESET (out), C13 DDR_WEn (out), C14 DDR_BA2 (out), C15 DDR_A3 (out), C17 DDR_A5 (out), C18 DDR_A9 (out), C19 DDR_A13 (out), C20 DDR_ODT1 (out), C21 DDR_DM2 (out), C22 DDR_D17 (io), D7 DDR_D25 (io), D8 DDR_D29 (io), D10 DDR_D12 (io), D11 DDR_CKE1 (out), D13 DDR_CASn (out), D14 DDR_RASn (out), D16 DDR_A14 (out), D17 DDR_D19 (io), D18 DDR_A10 (out), D19 DDR_A12 (out), D21 DDR_D22 (io), D22 DDR_D23 (io), D23 DDR_DM0 (out), E7 DDR_DM3 (out), E8 DDR_D28 (io), E10 DDR_D30 (io), E11 DDR_D13 (io), E13 DDR_CS1 (out), E14 DDR_A2 (out), E16 DDR_D18 (io), E17 DDR_D0 (io), E18 DDR_D3 (io), E20 DDR_D2 (io), E21 DDR_D1 (io), E22 DDR_DQS0 (out), E23 DDR_DQS0n (out), F10 MVDD1 (power), F11 MVDD2 (power), F13 DDR_VREF (power), F14 MVDD3 (power), F16 MVDD4 (power), F17 MVDD5 (power), F19 DDR_D4 (io), F20 DDR_D7 (io), F21 DDR_D5 (io), F22 DDR_D6 (io), G10 MVDD6 (power), G13 MVDD7 (power), G14 MVDD8 (power), G15 DDR_PZQ (in), H18 DDR_A15
part M pins: G11 CVDD1 (power), G16 CVDD2 (power), H7 CVDD3 (power), H17 VCCIO2 (power), J17 CVDD4 (power), K17 VCCIO1 (power), L17 CVDD5 (power), N5 AVDD1 (power), N7 CVDD6 (power), P5 AVDD2 (power), P6 AVDD3 (power), P17 CVDD7 (power), T5 AVDD4 (power), T6 AVDD5 (power), T17 CVDD8 (power), U5 AVDD6 (power), U6 AVDD7 (power), U8 AVDD9 (power), U9 AVDD10 (power), V5 AVDD8 (power), V7 AVDD11 (power), V8 AVDD12 (power), V10 AVDD_COM (out)
part N pins: AA16 VSS86 (power), AA17 VSS87 (power), AB10 VSS88 (power), B3 VSS89 (power), B6 VSS90 (power), C5 VSS91 (power), C16 VSS1 (power), D20 VSS2 (power), G12 VSS3 (power), H8 VSS4 (power), H9 VSS5 (power), H10 VSS6 (power), H11 VSS7 (power), H12 VSS8 (power), H13 VSS9 (power), H14 VSS10 (power), H15 VSS11 (power), H16 VSS12 (power), J8 VSS13 (power), J9 VSS14 (power), J10 VSS15 (power), J11 VSS16 (power), J12 VSS17 (power), J13 VSS18 (power), J14 VSS19 (power), J15 VSS20 (power), J16 VSS21 (power), K8 VSS22 (power), K9 VSS23 (power), K10 VSS24 (power), K11 VSS25 (power), K12 VSS26 (power), K13 VSS27 (power), K14 VSS28 (power), K15 VSS29 (power), K16 VSS30 (power), L8 VSS31 (power), L9 VSS32 (power), L10 VSS33 (power), L11 VSS34 (power), L12 VSS35 (power), L13 VSS36 (power), L14 VSS37 (power), L15 VSS38 (power), L16 VSS39 (power), M8 VSS40 (power), M9 VSS41 (power), M10 VSS42 (power), M11 VSS43 (power), M12 VSS44 (power), M13 VSS45 (power), M14 VSS46 (power), M15 VSS47 (power), M16 VSS48 (power), M17 VSS49 (power), N8 VSS50 (power), N9 VSS51 (power), N10 VSS52 (power), N11 VSS53 (power), N12 VSS54 (power), N13 VSS55 (power), N14 VSS56 (power), N15 VSS57 (power), N16 VSS58 (power), P7 VSS59 (power), P8 VSS60 (power), P9 VSS61 (power), P10 VSS62 (power), P11 VSS63 (power), P12 VSS64 (power), P13 VSS65 (power), P14 VSS66 (power), P15 VSS67 (power), P16 VSS68 (power), R7 VSS69 (power), R8 VSS70 (power), R9 VSS71 (power), R10 VSS72 (power), R11 VSS73 (power), R12 VSS74 (power), R13 VSS75 (power), R14 VSS76 (power), R15 VSS77 (power), R16 VSS78 (power), T7 VSS79 (power), T8 VSS80 (power), T9 VSS81 (power), T10 VSS82 (power), T14 VSS83 (power), T15 VSS84 (power), T16 VSS85 (power)

## RL5877_0
designator U?, comment RL5877  (value not drawn)
Altium-Right: 210
pins: 1 MDIP0, 2 MDIN0, 3 AVDD10(NC), 4 MDIP1, 5 MDIN1, 6 MDIP2(NC), 7 MDIN2(NC), 8 AVDD10_0, 9 MDIP3(NC), 10 MDIN3(NC), 11 AVDD33(NC), 12 CLKREQB, 13 HSIP (power), 14 HSIN (power), 15 REFCLK_P, 16 REFCLK_N, 17 HSOP, 18 HSON, 19 PERSTB, 20 ISOLATEB, 21 LANWAKEB, 22 DVDD10(NC) (hiz), 23 VDDREG(DVDD33), 24 REGOUT(NC), 25 LED2(LED1), 26 LED1/GPO (hiz), 27 LED0, 28 CKXTAL1, 29 CKXTAL2, 30 AVDD10_1, 31 RSET, 32 AVDD33, 33 GND

## RN_0
designator RN?
Altium-Right: 20; Altium-Bottom: 50
pins: 1, 2, 3, 4, 5, 6, 7, 8

## RN_1
designator RN?
Altium-Right: 20; Altium-Bottom: 50
pins: 1, 2, 3, 4, 5, 6, 7, 8

## RN_2
designator RN?
Altium-Right: 20; Altium-Bottom: 50
pins: 1, 2, 3, 4, 5, 6, 7, 8

## RN_3
designator RN?
Altium-Right: 20; Altium-Bottom: 50
pins: 1, 2, 3, 4, 5, 6, 7, 8

## RN_0402X4
designator RN?
Altium-Right: 20; Altium-Bottom: 50
pins: 1, 2, 3, 4, 5, 6, 7, 8

## RTC-VBAT-2P
designator J?
Altium-Right: 20
pins: 1, 2

## S-NPN_0
designator Q?
Altium-Right: 40; Altium-Bottom: 20
pins: 1, 2, 3

## S-NPN_1
designator Q?
Altium-Right: 40; Altium-Bottom: 20
pins: 1, 2, 3

## Sensor_MPU6500_0
designator U?, comment BMI160
Altium-Right: 140; Altium-Bottom: 110
pins: 1 SDO, 2 ASDX, 3 ASCX, 4 INT1, 5 VDDIO, 6 GNDIO, 7 GND, 8 VDD, 9 INT2, 10 OCSB, 11 OSDO, 12 CSB, 13 SCX, 14 SDX

## Sensor_MPU6500_1
designator U?
Altium-Right: 130
pins: 1 NC#1, 2 NC#2, 3 NC#3, 4 NC#4, 5 NC#5, 6 NC#6, 7 AUX_CL, 8 VDDIO, 9 SDO/AD0, 10 REGOUT, 11 FSYNC, 12 INT, 13 VDD, 14 NC#7, 15 NC#8, 16 NC#9, 17 NC#10, 18 GND, 19 RESV1, 20 RESV2, 21 AUX_DA, 22 nCS, 23 SCL/SCLK, 24 SDA/SDI, 25 E-PAD

## SIM-SPPN08-XO-1X80_0
designator J?
Altium-Right: 120; Altium-Bottom: 100
footprint SIM-SPPN08-XO-1X80
pins: 1 VCC, 2 RST, 3 CLK, 4 VPP, 5 GND, 6 I/O, 7 DATA0, 8 MCMD, 9 CART_DET, 10 GND, 11 GND, 12 GND, 13 GND

## SIM-SPPN08-XO-1X80_1
designator J?
Altium-Right: 120; Altium-Bottom: 100
footprint SIM-SPPN08-XO-1X80
pins: 1 VCC, 2 GND, 3 RST, 4 VPP, 5 CLK, 6 I/O, 7 DATA0, 8 MCMD, 9 CART_DET, 10 GND, 11 GND, 12 GND, 13 GND

## SMB137B_0
designator U?
Altium-Right: 100; Altium-Bottom: 290
pins: A1 DCIN, A2 DCIN, A3 DCIN, A4 THERM, A5 EN, A6 SCL, B1 FETDRV, B2 VOUT, B3 VOUT, B4 VOUTL, B5 SDA, B6 STAT, C1 OTG/LBR, C2 USBIN, C3 SW, C4 SW, C5 SW, C6 USB5/1/HC, D1 NC, D2 USBIN, D3 GND, D4 GND, D5 GND, D6 CSOUT, E1 AUXPWR, E2 USBIN, E3 CSIN, E4 D+, E5 D-, E6 CSOUT

## SMB347_0
designator U?
Altium-Right: 100; Altium-Bottom: 250
footprint BGA30-3X2.5
pins: A1 USBIN, A2 MIDUSBIN, A3 SW, A4 MIDDCIN, A5 DCIN, B1 USBIN, B2 BOOT, B3 SW, B4 VCHG, B5 DCIN, C1 VDDCAP, C2 FETDRV, C3 THERM, C4 EN, C5 GND, D1 D-, D2 USB5/1/HC, D3 SUSP, D4 VSYS, D5 VSYS, E1 D+, E2 CHG_DET, E3 VBATT, E4 CHGOUT, E5 CHGOUT, F1 OTG/ID, F2 SCL, F3 SDA, F4 GND, F5 STAT

## SMB347_1
designator U?
Altium-Right: 100; Altium-Bottom: 250
footprint BGA30-3X2.5
pins: A1 USBIN, A2 MIDUSBIN, A3 SW, A4 MIDDCIN, A5 DCIN, B1 USBIN, B2 BOOT, B3 SW, B4 VCHG, B5 DCIN, C1 VDDCAP, C2 FETDRV, C3 THERM, C4 EN, C5 GND, D1 D-, D2 USB5/1/HC, D3 SUSP, D4 VSYS, D5 VSYS, E1 D+, E2 CHG_DET, E3 VBATT, E4 CHGOUT, E5 CHGOUT, F1 OTG/ID, F2 SCL, F3 SDA, F4 GND, F5 STAT

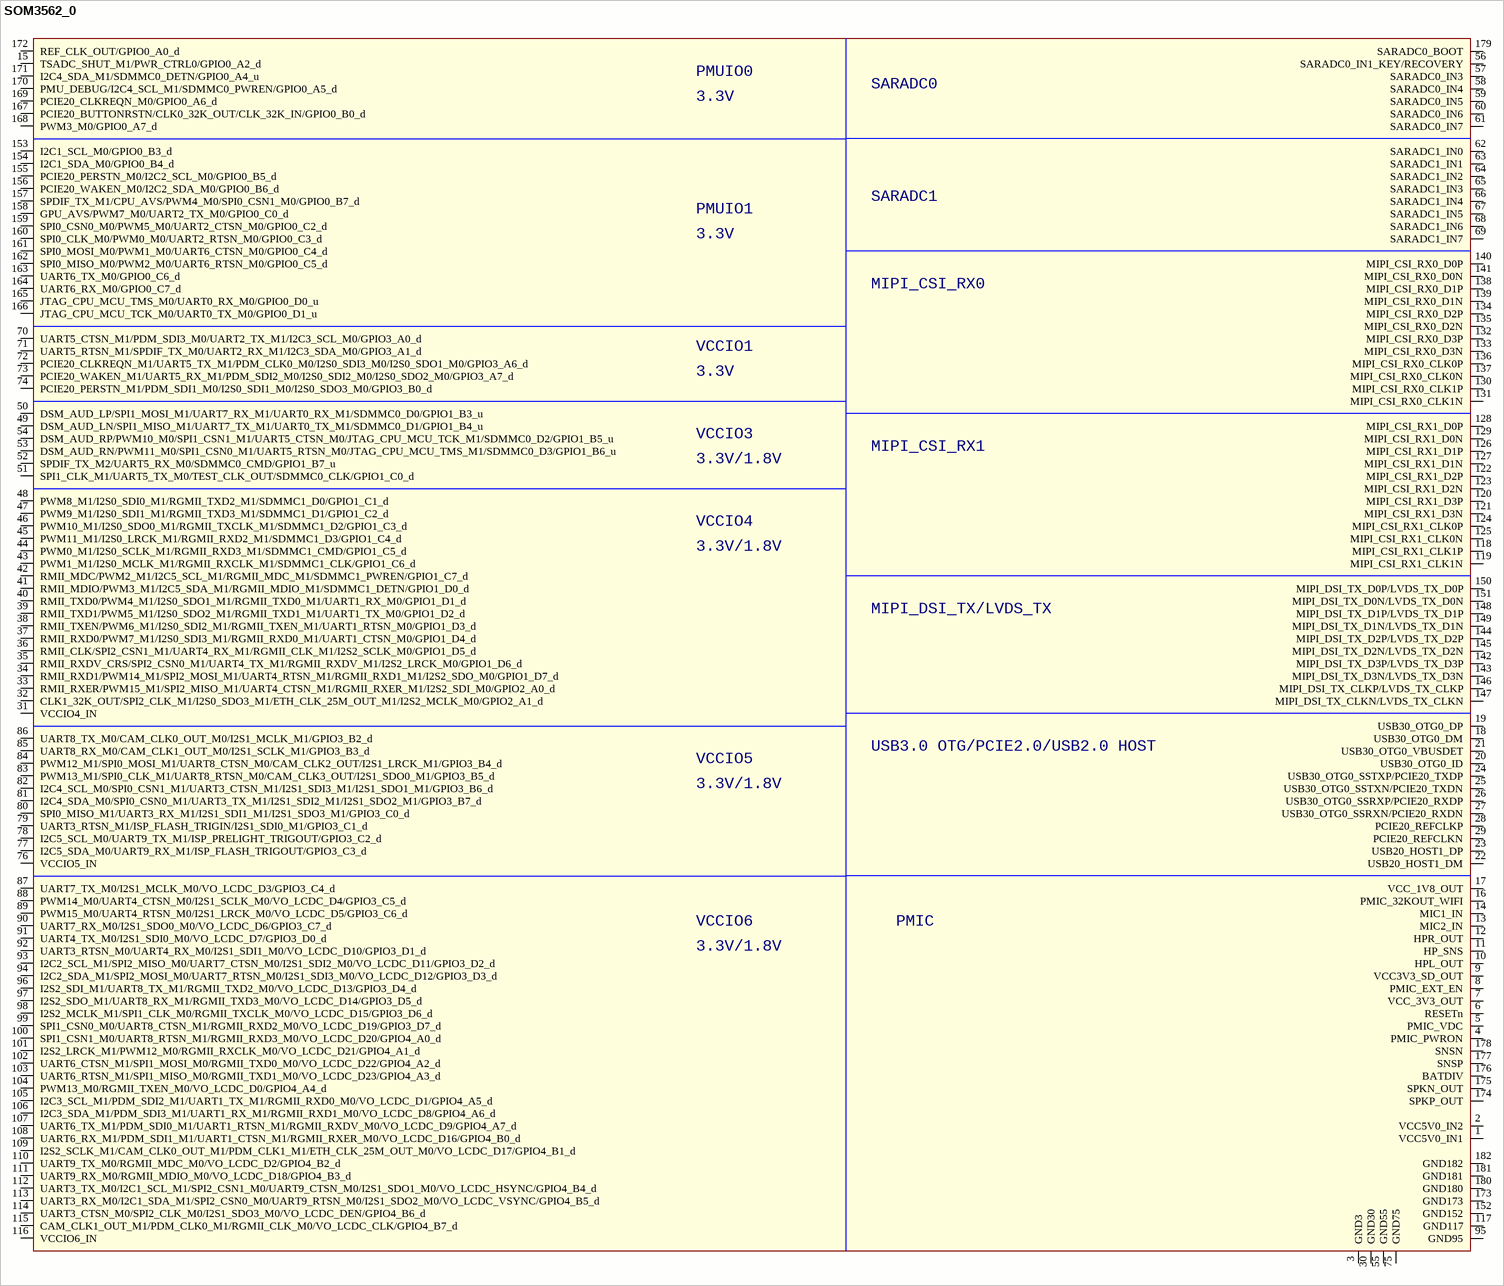
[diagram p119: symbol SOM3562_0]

## SOM3562_0
designator M?
Altium-Right: 1150; Altium-Bottom: 970
footprint SOM3562-182P
pins: 1 VCC5V0_IN1, 2 VCC5V0_IN2, 3 GND3, 4 PMIC_PWRON, 5 PMIC_VDC, 6 RESETn, 7 VCC_3V3_OUT, 8 PMIC_EXT_EN, 9 VCC3V3_SD_OUT, 10 HPL_OUT, 11 HP_SNS, 12 HPR_OUT, 13 MIC2_IN, 14 MIC1_IN, 15 TSADC_SHUT_M1/PWR_CTRL0/GPIO0_A2_d, 16 PMIC_32KOUT_WIFI, 17 VCC_1V8_OUT, 18 USB30_OTG0_DM, 19 USB30_OTG0_DP, 20 USB30_OTG0_ID, 21 USB30_OTG0_VBUSDET, 22 USB20_HOST1_DM, 23 USB20_HOST1_DP, 24 USB30_OTG0_SSTXP/PCIE20_TXDP, 25 USB30_OTG0_SSTXN/PCIE20_TXDN, 26 USB30_OTG0_SSRXP/PCIE20_RXDP, 27 USB30_OTG0_SSRXN/PCIE20_RXDN, 28 PCIE20_REFCLKP, 29 PCIE20_REFCLKN, 30 GND30, 31 VCCIO4_IN, 32 CLK1_32K_OUT/SPI2_CLK_M1/I2S0_SDO3_M1/ETH_CLK_25M_OUT_M1/I2S2_MCLK_M0/GPIO2_A1_d, 33 RMII_RXER/PWM15_M1/SPI2_MISO_M1/UART4_CTSN_M1/RGMII_RXER_M1/I2S2_SDI_M0/GPIO2_A0_d, 34 RMII_RXD1/PWM14_M1/SPI2_MOSI_M1/UART4_RTSN_M1/RGMII_RXD1_M1/I2S2_SDO_M0/GPIO1_D7_d, 35 RMII_RXDV_CRS/SPI2_CSN0_M1/UART4_TX_M1/RGMII_RXDV_M1/I2S2_LRCK_M0/GPIO1_D6_d, 36 RMII_CLK/SPI2_CSN1_M1/UART4_RX_M1/RGMII_CLK_M1/I2S2_SCLK_M0/GPIO1_D5_d, 37 RMII_RXD0/PWM7_M1/I2S0_SDI3_M1/RGMII_RXD0_M1/UART1_CTSN_M0/GPIO1_D4_d, 38 RMII_TXEN/PWM6_M1/I2S0_SDI2_M1/RGMII_TXEN_M1/UART1_RTSN_M0/GPIO1_D3_d, 39 RMII_TXD1/PWM5_M1/I2S0_SDO2_M1/RGMII_TXD1_M1/UART1_TX_M0/GPIO1_D2_d, 40 RMII_TXD0/PWM4_M1/I2S0_SDO1_M1/RGMII_TXD0_M1/UART1_RX_M0/GPIO1_D1_d, 41 RMII_MDIO/PWM3_M1/I2C5_SDA_M1/RGMII_MDIO_M1/SDMMC1_DETN/GPIO1_D0_d, 42 RMII_MDC/PWM2_M1/I2C5_SCL_M1/RGMII_MDC_M1/SDMMC1_PWREN/GPIO1_C7_d, 43 PWM1_M1/I2S0_MCLK_M1/RGMII_RXCLK_M1/SDMMC1_CLK/GPIO1_C6_d, 44 PWM0_M1/I2S0_SCLK_M1/RGMII_RXD3_M1/SDMMC1_CMD/GPIO1_C5_d, 45 PWM11_M1/I2S0_LRCK_M1/RGMII_RXD2_M1/SDMMC1_D3/GPIO1_C4_d, 46 PWM10_M1/I2S0_SDO0_M1/RGMII_TXCLK_M1/SDMMC1_D2/GPIO1_C3_d, 47 PWM9_M1/I2S0_SDI1_M1/RGMII_TXD3_M1/SDMMC1_D1/GPIO1_C2_d, 48 PWM8_M1/I2S0_SDI0_M1/RGMII_TXD2_M1/SDMMC1_D0/GPIO1_C1_d, 49 DSM_AUD_LN/SPI1_MISO_M1/UART7_TX_M1/UART0_TX_M1/SDMMC0_D1/GPIO1_B4_u, 50 DSM_AUD_LP/SPI1_MOSI_M1/UART7_RX_M1/UART0_RX_M1/SDMMC0_D0/GPIO1_B3_u, 51 SPI1_CLK_M1/UART5_TX_M0/TEST_CLK_OUT/SDMMC0_CLK/GPIO1_C0_d, 52 SPDIF_TX_M2/UART5_RX_M0/SDMMC0_CMD/GPIO1_B7_u, 53 DSM_AUD_RN/PWM11_M0/SPI1_CSN0_M1/UART5_RTSN_M0/JTAG_CPU_MCU_TMS_M1/SDMMC0_D3/GPIO1_B6_u, 54 DSM_AUD_RP/PWM10_M0/SPI1_CSN1_M1/UART5_CTSN_M0/JTAG_CPU_MCU_TCK_M1/SDMMC0_D2/GPIO1_B5_u, 55 GND55, 56 SARADC0_IN1_KEY/RECOVERY, 57 SARADC0_IN3, 58 SARADC0_IN4, 59 SARADC0_IN5, 60 SARADC0_IN6, 61 SARADC0_IN7, 62 SARADC1_IN0, 63 SARADC1_IN1, 64 SARADC1_IN2, 65 SARADC1_IN3, 66 SARADC1_IN4, 67 SARADC1_IN5, 68 SARADC1_IN6, 69 SARADC1_IN7, 70 UART5_CTSN_M1/PDM_SDI3_M0/UART2_TX_M1/I2C3_SCL_M0/GPIO3_A0_d, 71 UART5_RTSN_M1/SPDIF_TX_M0/UART2_RX_M1/I2C3_SDA_M0/GPIO3_A1_d, 72 PCIE20_CLKREQN_M1/UART5_TX_M1/PDM_CLK0_M0/I2S0_SDI3_M0/I2S0_SDO1_M0/GPIO3_A6_d, 73 PCIE20_WAKEN_M1/UART5_RX_M1/PDM_SDI2_M0/I2S0_SDI2_M0/I2S0_SDO2_M0/GPIO3_A7_d, 74 PCIE20_PERSTN_M1/PDM_SDI1_M0/I2S0_SDI1_M0/I2S0_SDO3_M0/GPIO3_B0_d, 75 GND75, 76 VCCIO5_IN, 77 I2C5_SDA_M0/UART9_RX_M1/ISP_FLASH_TRIGOUT/GPIO3_C3_d, 78 I2C5_SCL_M0/UART9_TX_M1/ISP_PRELIGHT_TRIGOUT/GPIO3_C2_d, 79 UART3_RTSN_M1/ISP_FLASH_TRIGIN/I2S1_SDI0_M1/GPIO3_C1_d, 80 SPI0_MISO_M1/UART3_RX_M1/I2S1_SDI1_M1/I2S1_SDO3_M1/GPIO3_C0_d, 81 I2C4_SDA_M0/SPI0_CSN0_M1/UART3_TX_M1/I2S1_SDI2_M1/I2S1_SDO2_M1/GPIO3_B7_d, 82 I2C4_SCL_M0/SPI0_CSN1_M1/UART3_CTSN_M1/I2S1_SDI3_M1/I2S1_SDO1_M1/GPIO3_B6_d, 83 PWM13_M1/SPI0_CLK_M1/UART8_RTSN_M0/CAM_CLK3_OUT/I2S1_SDO0_M1/GPIO3_B5_d, 84 PWM12_M1/SPI0_MOSI_M1/UART8_CTSN_M0/CAM_CLK2_OUT/I2S1_LRCK_M1/GPIO3_B4_d, 85 UART8_RX_M0/CAM_CLK1_OUT_M0/I2S1_SCLK_M1/GPIO3_B3_d, 86 UART8_TX_M0/CAM_CLK0_OUT_M0/I2S1_MCLK_M1/GPIO3_B2_d, 87 UART7_TX_M0/I2S1_MCLK_M0/VO_LCDC_D3/GPIO3_C4_d, 88 PWM14_M0/UART4_CTSN_M0/I2S1_SCLK_M0/VO_LCDC_D4/GPIO3_C5_d, 89 PWM15_M0/UART4_RTSN_M0/I2S1_LRCK_M0/VO_LCDC_D5/GPIO3_C6_d, 90 UART7_RX_M0/I2S1_SDO0_M0/VO_LCDC_D6/GPIO3_C7_d, 91 UART4_TX_M0/I2S1_SDI0_M0/VO_LCDC_D7/GPIO3_D0_d, 92 UART3_RTSN_M0/UART4_RX_M0/I2S1_SDI1_M0/VO_LCDC_D10/GPIO3_D1_d, 93 I2C2_SCL_M1/SPI2_MISO_M0/UART7_CTSN_M0/I2S1_SDI2_M0/VO_LCDC_D11/GPIO3_D2_d, 94 I2C2_SDA_M1/SPI2_MOSI_M0/UART7_RTSN_M0/I2S1_SDI3_M0/VO_LCDC_D12/GPIO3_D3_d, 95 GND95, 96 I2S2_SDI_M1/UART8_TX_M1/RGMII_TXD2_M0/VO_LCDC_D13/GPIO3_D4_d, 97 I2S2_SDO_M1/UART8_RX_M1/RGMII_TXD3_M0/VO_LCDC_D14/GPIO3_D5_d, 98 I2S2_MCLK_M1/SPI1_CLK_M0/RGMII_TXCLK_M0/VO_LCDC_D15/GPIO3_D6_d, 99 SPI1_CSN0_M0/UART8_CTSN_M1/RGMII_RXD2_M0/VO_LCDC_D19/GPIO3_D7_d, 100 SPI1_CSN1_M0/UART8_RTSN_M1/RGMII_RXD3_M0/VO_LCDC_D20/GPIO4_A0_d, 101 I2S2_LRCK_M1/PWM12_M0/RGMII_RXCLK_M0/VO_LCDC_D21/GPIO4_A1_d, 102 UART6_CTSN_M1/SPI1_MOSI_M0/RGMII_TXD0_M0/VO_LCDC_D22/GPIO4_A2_d, 103 UART6_RTSN_M1/SPI1_MISO_M0/RGMII_TXD1_M0/VO_LCDC_D23/GPIO4_A3_d, 104 PWM13_M0/RGMII_TXEN_M0/VO_LCDC_D0/GPIO4_A4_d, 105 I2C3_SCL_M1/PDM_SDI2_M1/UART1_TX_M1/RGMII_RXD0_M0/VO_LCDC_D1/GPIO4_A5_d, 106 I2C3_SDA_M1/PDM_SDI3_M1/UART1_RX_M1/RGMII_RXD1_M0/VO_LCDC_D8/GPIO4_A6_d, 107 UART6_TX_M1/PDM_SDI0_M1/UART1_RTSN_M1/RGMII_RXDV_M0/VO_LCDC_D9/GPIO4_A7_d, 108 UART6_RX_M1/PDM_SDI1_M1/UART1_CTSN_M1/RGMII_RXER_M0/VO_LCDC_D16/GPIO4_B0_d, 109 I2S2_SCLK_M1/CAM_CLK0_OUT_M1/PDM_CLK1_M1/ETH_CLK_25M_OUT_M0/VO_LCDC_D17/GPIO4_B1_d, 110 UART9_TX_M0/RGMII_MDC_M0/VO_LCDC_D2/GPIO4_B2_d, 111 UART9_RX_M0/RGMII_MDIO_M0/VO_LCDC_D18/GPIO4_B3_d, 112 UART3_TX_M0/I2C1_SCL_M1/SPI2_CSN1_M0/UART9_CTSN_M0/I2S1_SDO1_M0/VO_LCDC_HSYNC/GPIO4_B4_d, 113 UART3_RX_M0/I2C1_SDA_M1/SPI2_CSN0_M0/UART9_RTSN_M0/I2S1_SDO2_M0/VO_LCDC_VSYNC/GPIO4_B5_d, 114 UART3_CTSN_M0/SPI2_CLK_M0/I2S1_SDO3_M0/VO_LCDC_DEN/GPIO4_B6_d, 115 CAM_CLK1_OUT_M1/PDM_CLK0_M1/RGMII_CLK_M0/VO_LCDC_CLK/GPIO4_B7_d, 116 VCCIO6_IN, 117 GND117, 118 MIPI_CSI_RX1_CLK1P, 119 MIPI_CSI_RX1_CLK1N, 120 MIPI_CSI_RX1_D3P, 121 MIPI_CSI_RX1_D3N, 122 MIPI_CSI_RX1_D2P, 123 MIPI_CSI_RX1_D2N, 124 MIPI_CSI_RX1_CLK0P, 125 MIPI_CSI_RX1_CLK0N, 126 MIPI_CSI_RX1_D1P, 127 MIPI_CSI_RX1_D1N, 128 MIPI_CSI_RX1_D0P, 129 MIPI_CSI_RX1_D0N, 130 MIPI_CSI_RX0_CLK1P, 131 MIPI_CSI_RX0_CLK1N, 132 MIPI_CSI_RX0_D3P, 133 MIPI_CSI_RX0_D3N, 134 MIPI_CSI_RX0_D2P, 135 MIPI_CSI_RX0_D2N, 136 MIPI_CSI_RX0_CLK0P, 137 MIPI_CSI_RX0_CLK0N, 138 MIPI_CSI_RX0_D1P, 139 MIPI_CSI_RX0_D1N, 140 MIPI_CSI_RX0_D0P, 141 MIPI_CSI_RX0_D0N, 142 MIPI_DSI_TX_D3P/LVDS_TX_D3P, 143 MIPI_DSI_TX_D3N/LVDS_TX_D3N, 144 MIPI_DSI_TX_D2P/LVDS_TX_D2P, 145 MIPI_DSI_TX_D2N/LVDS_TX_D2N, 146 MIPI_DSI_TX_CLKP/LVDS_TX_CLKP, 147 MIPI_DSI_TX_CLKN/LVDS_TX_CLKN, 148 MIPI_DSI_TX_D1P/LVDS_TX_D1P, 149 MIPI_DSI_TX_D1N/LVDS_TX_D1N, 150 MIPI_DSI_TX_D0P/LVDS_TX_D0P, 151 MIPI_DSI_TX_D0N/LVDS_TX_D0N, 152 GND152, 153 I2C1_SCL_M0/GPIO0_B3_d, 154 I2C1_SDA_M0/GPIO0_B4_d, 155 PCIE20_PERSTN_M0/I2C2_SCL_M0/GPIO0_B5_d, 156 PCIE20_WAKEN_M0/I2C2_SDA_M0/GPIO0_B6_d, 157 SPDIF_TX_M1/CPU_AVS/PWM4_M0/SPI0_CSN1_M0/GPIO0_B7_d, 158 GPU_AVS/PWM7_M0/UART2_TX_M0/GPIO0_C0_d, 159 SPI0_CSN0_M0/PWM5_M0/UART2_CTSN_M0/GPIO0_C2_d, 160 SPI0_CLK_M0/PWM0_M0/UART2_RTSN_M0/GPIO0_C3_d, 161 SPI0_MOSI_M0/PWM1_M0/UART6_CTSN_M0/GPIO0_C4_d, 162 SPI0_MISO_M0/PWM2_M0/UART6_RTSN_M0/GPIO0_C5_d, 163 UART6_TX_M0/GPIO0_C6_d, 164 UART6_RX_M0/GPIO0_C7_d, 165 JTAG_CPU_MCU_TMS_M0/UART0_RX_M0/GPIO0_D0_u, 166 JTAG_CPU_MCU_TCK_M0/UART0_TX_M0/GPIO0_D1_u, 167 PCIE20_BUTTONRSTN/CLK0_32K_OUT/CLK_32K_IN/GPIO0_B0_d, 168 PWM3_M0/GPIO0_A7_d, 169 PCIE20_CLKREQN_M0/GPIO0_A6_d, 170 PMU_DEBUG/I2C4_SCL_M1/SDMMC0_PWREN/GPIO0_A5_d, 171 I2C4_SDA_M1/SDMMC0_DETN/GPIO0_A4_u, 172 REF_CLK_OUT/GPIO0_A0_d, 173 GND173, 174 SPKP_OUT, 175 SPKN_OUT, 176 BATDIV, 177 SNSP, 178 SNSN, 179 SARADC0_BOOT, 180 GND180, 181 GND181, 182 GND182

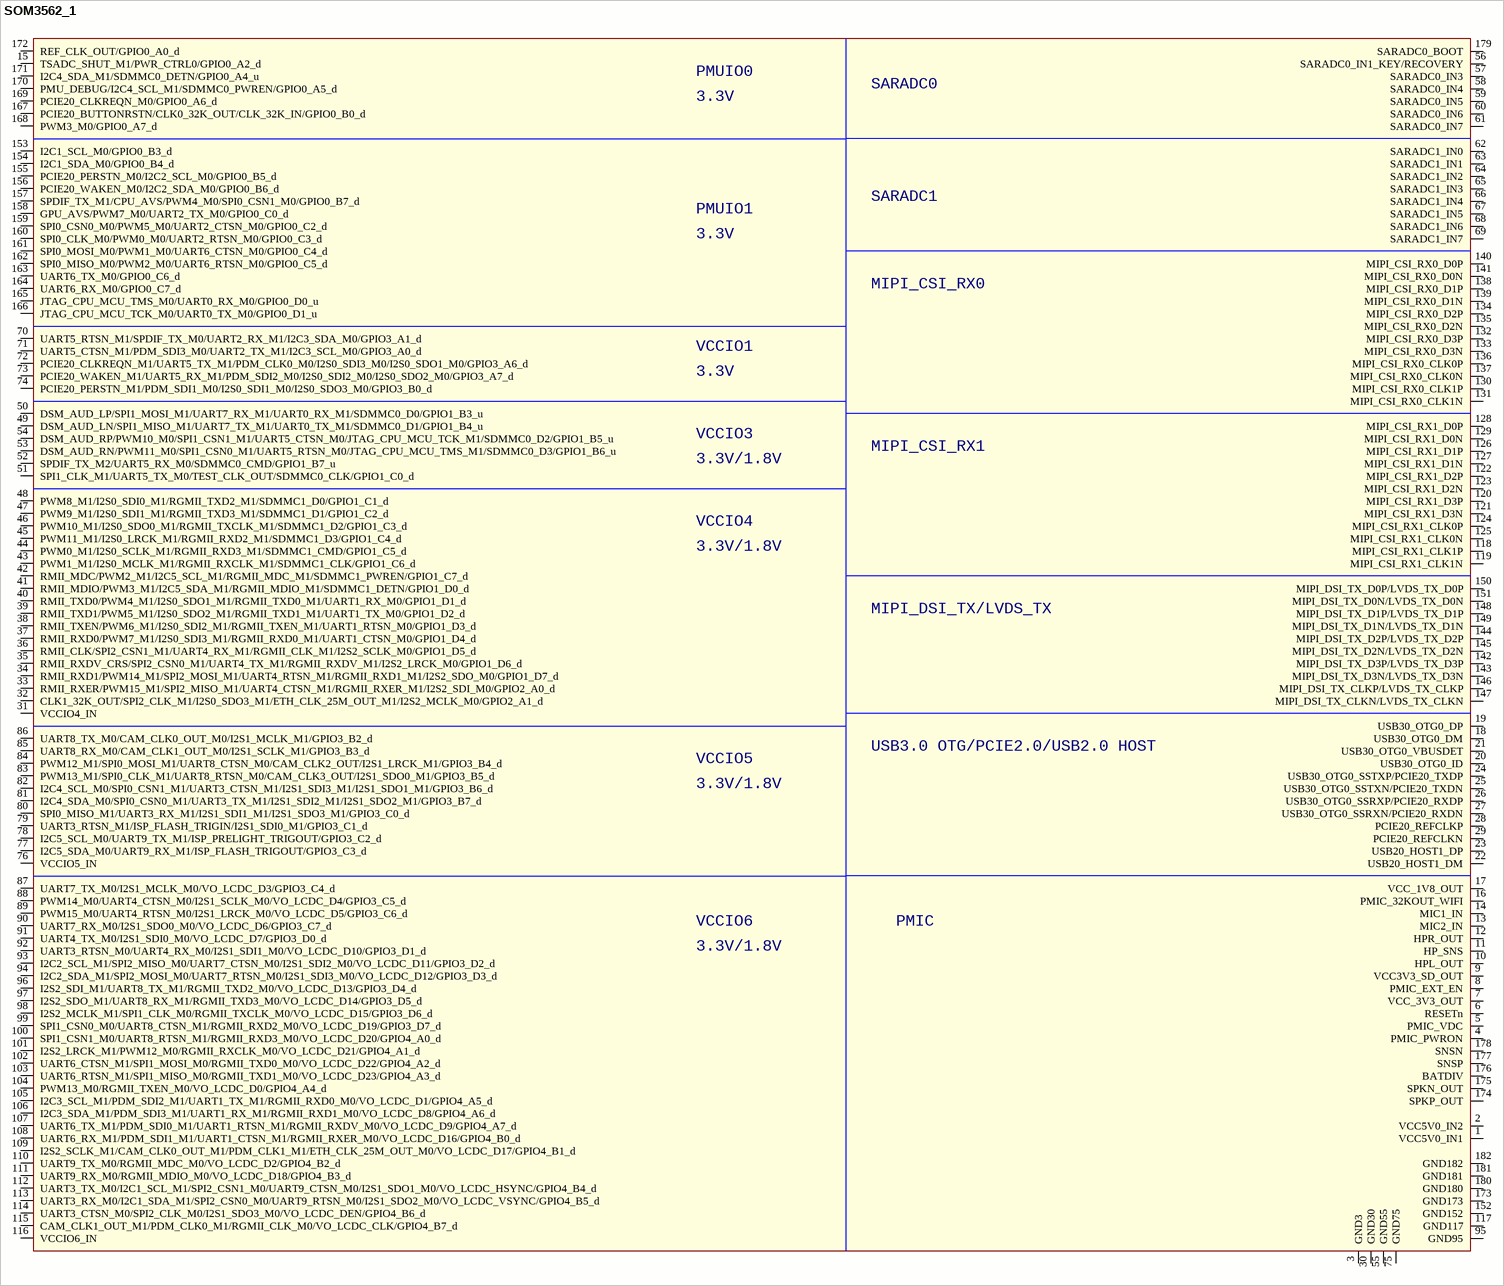
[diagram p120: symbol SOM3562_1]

## SOM3562_1
designator M?
Altium-Right: 1150; Altium-Bottom: 970
footprint SOM3562-182P
pins: 1 VCC5V0_IN1, 2 VCC5V0_IN2, 3 GND3, 4 PMIC_PWRON, 5 PMIC_VDC, 6 RESETn, 7 VCC_3V3_OUT, 8 PMIC_EXT_EN, 9 VCC3V3_SD_OUT, 10 HPL_OUT, 11 HP_SNS, 12 HPR_OUT, 13 MIC2_IN, 14 MIC1_IN, 15 TSADC_SHUT_M1/PWR_CTRL0/GPIO0_A2_d, 16 PMIC_32KOUT_WIFI, 17 VCC_1V8_OUT, 18 USB30_OTG0_DM, 19 USB30_OTG0_DP, 20 USB30_OTG0_ID, 21 USB30_OTG0_VBUSDET, 22 USB20_HOST1_DM, 23 USB20_HOST1_DP, 24 USB30_OTG0_SSTXP/PCIE20_TXDP, 25 USB30_OTG0_SSTXN/PCIE20_TXDN, 26 USB30_OTG0_SSRXP/PCIE20_RXDP, 27 USB30_OTG0_SSRXN/PCIE20_RXDN, 28 PCIE20_REFCLKP, 29 PCIE20_REFCLKN, 30 GND30, 31 VCCIO4_IN, 32 CLK1_32K_OUT/SPI2_CLK_M1/I2S0_SDO3_M1/ETH_CLK_25M_OUT_M1/I2S2_MCLK_M0/GPIO2_A1_d, 33 RMII_RXER/PWM15_M1/SPI2_MISO_M1/UART4_CTSN_M1/RGMII_RXER_M1/I2S2_SDI_M0/GPIO2_A0_d, 34 RMII_RXD1/PWM14_M1/SPI2_MOSI_M1/UART4_RTSN_M1/RGMII_RXD1_M1/I2S2_SDO_M0/GPIO1_D7_d, 35 RMII_RXDV_CRS/SPI2_CSN0_M1/UART4_TX_M1/RGMII_RXDV_M1/I2S2_LRCK_M0/GPIO1_D6_d, 36 RMII_CLK/SPI2_CSN1_M1/UART4_RX_M1/RGMII_CLK_M1/I2S2_SCLK_M0/GPIO1_D5_d, 37 RMII_RXD0/PWM7_M1/I2S0_SDI3_M1/RGMII_RXD0_M1/UART1_CTSN_M0/GPIO1_D4_d, 38 RMII_TXEN/PWM6_M1/I2S0_SDI2_M1/RGMII_TXEN_M1/UART1_RTSN_M0/GPIO1_D3_d, 39 RMII_TXD1/PWM5_M1/I2S0_SDO2_M1/RGMII_TXD1_M1/UART1_TX_M0/GPIO1_D2_d, 40 RMII_TXD0/PWM4_M1/I2S0_SDO1_M1/RGMII_TXD0_M1/UART1_RX_M0/GPIO1_D1_d, 41 RMII_MDIO/PWM3_M1/I2C5_SDA_M1/RGMII_MDIO_M1/SDMMC1_DETN/GPIO1_D0_d, 42 RMII_MDC/PWM2_M1/I2C5_SCL_M1/RGMII_MDC_M1/SDMMC1_PWREN/GPIO1_C7_d, 43 PWM1_M1/I2S0_MCLK_M1/RGMII_RXCLK_M1/SDMMC1_CLK/GPIO1_C6_d, 44 PWM0_M1/I2S0_SCLK_M1/RGMII_RXD3_M1/SDMMC1_CMD/GPIO1_C5_d, 45 PWM11_M1/I2S0_LRCK_M1/RGMII_RXD2_M1/SDMMC1_D3/GPIO1_C4_d, 46 PWM10_M1/I2S0_SDO0_M1/RGMII_TXCLK_M1/SDMMC1_D2/GPIO1_C3_d, 47 PWM9_M1/I2S0_SDI1_M1/RGMII_TXD3_M1/SDMMC1_D1/GPIO1_C2_d, 48 PWM8_M1/I2S0_SDI0_M1/RGMII_TXD2_M1/SDMMC1_D0/GPIO1_C1_d, 49 DSM_AUD_LN/SPI1_MISO_M1/UART7_TX_M1/UART0_TX_M1/SDMMC0_D1/GPIO1_B4_u, 50 DSM_AUD_LP/SPI1_MOSI_M1/UART7_RX_M1/UART0_RX_M1/SDMMC0_D0/GPIO1_B3_u, 51 SPI1_CLK_M1/UART5_TX_M0/TEST_CLK_OUT/SDMMC0_CLK/GPIO1_C0_d, 52 SPDIF_TX_M2/UART5_RX_M0/SDMMC0_CMD/GPIO1_B7_u, 53 DSM_AUD_RN/PWM11_M0/SPI1_CSN0_M1/UART5_RTSN_M0/JTAG_CPU_MCU_TMS_M1/SDMMC0_D3/GPIO1_B6_u, 54 DSM_AUD_RP/PWM10_M0/SPI1_CSN1_M1/UART5_CTSN_M0/JTAG_CPU_MCU_TCK_M1/SDMMC0_D2/GPIO1_B5_u, 55 GND55, 56 SARADC0_IN1_KEY/RECOVERY, 57 SARADC0_IN3, 58 SARADC0_IN4, 59 SARADC0_IN5, 60 SARADC0_IN6, 61 SARADC0_IN7, 62 SARADC1_IN0, 63 SARADC1_IN1, 64 SARADC1_IN2, 65 SARADC1_IN3, 66 SARADC1_IN4, 67 SARADC1_IN5, 68 SARADC1_IN6, 69 SARADC1_IN7, 70 UART5_RTSN_M1/SPDIF_TX_M0/UART2_RX_M1/I2C3_SDA_M0/GPIO3_A1_d, 71 UART5_CTSN_M1/PDM_SDI3_M0/UART2_TX_M1/I2C3_SCL_M0/GPIO3_A0_d, 72 PCIE20_CLKREQN_M1/UART5_TX_M1/PDM_CLK0_M0/I2S0_SDI3_M0/I2S0_SDO1_M0/GPIO3_A6_d, 73 PCIE20_WAKEN_M1/UART5_RX_M1/PDM_SDI2_M0/I2S0_SDI2_M0/I2S0_SDO2_M0/GPIO3_A7_d, 74 PCIE20_PERSTN_M1/PDM_SDI1_M0/I2S0_SDI1_M0/I2S0_SDO3_M0/GPIO3_B0_d, 75 GND75, 76 VCCIO5_IN, 77 I2C5_SDA_M0/UART9_RX_M1/ISP_FLASH_TRIGOUT/GPIO3_C3_d, 78 I2C5_SCL_M0/UART9_TX_M1/ISP_PRELIGHT_TRIGOUT/GPIO3_C2_d, 79 UART3_RTSN_M1/ISP_FLASH_TRIGIN/I2S1_SDI0_M1/GPIO3_C1_d, 80 SPI0_MISO_M1/UART3_RX_M1/I2S1_SDI1_M1/I2S1_SDO3_M1/GPIO3_C0_d, 81 I2C4_SDA_M0/SPI0_CSN0_M1/UART3_TX_M1/I2S1_SDI2_M1/I2S1_SDO2_M1/GPIO3_B7_d, 82 I2C4_SCL_M0/SPI0_CSN1_M1/UART3_CTSN_M1/I2S1_SDI3_M1/I2S1_SDO1_M1/GPIO3_B6_d, 83 PWM13_M1/SPI0_CLK_M1/UART8_RTSN_M0/CAM_CLK3_OUT/I2S1_SDO0_M1/GPIO3_B5_d, 84 PWM12_M1/SPI0_MOSI_M1/UART8_CTSN_M0/CAM_CLK2_OUT/I2S1_LRCK_M1/GPIO3_B4_d, 85 UART8_RX_M0/CAM_CLK1_OUT_M0/I2S1_SCLK_M1/GPIO3_B3_d, 86 UART8_TX_M0/CAM_CLK0_OUT_M0/I2S1_MCLK_M1/GPIO3_B2_d, 87 UART7_TX_M0/I2S1_MCLK_M0/VO_LCDC_D3/GPIO3_C4_d, 88 PWM14_M0/UART4_CTSN_M0/I2S1_SCLK_M0/VO_LCDC_D4/GPIO3_C5_d, 89 PWM15_M0/UART4_RTSN_M0/I2S1_LRCK_M0/VO_LCDC_D5/GPIO3_C6_d, 90 UART7_RX_M0/I2S1_SDO0_M0/VO_LCDC_D6/GPIO3_C7_d, 91 UART4_TX_M0/I2S1_SDI0_M0/VO_LCDC_D7/GPIO3_D0_d, 92 UART3_RTSN_M0/UART4_RX_M0/I2S1_SDI1_M0/VO_LCDC_D10/GPIO3_D1_d, 93 I2C2_SCL_M1/SPI2_MISO_M0/UART7_CTSN_M0/I2S1_SDI2_M0/VO_LCDC_D11/GPIO3_D2_d, 94 I2C2_SDA_M1/SPI2_MOSI_M0/UART7_RTSN_M0/I2S1_SDI3_M0/VO_LCDC_D12/GPIO3_D3_d, 95 GND95, 96 I2S2_SDI_M1/UART8_TX_M1/RGMII_TXD2_M0/VO_LCDC_D13/GPIO3_D4_d, 97 I2S2_SDO_M1/UART8_RX_M1/RGMII_TXD3_M0/VO_LCDC_D14/GPIO3_D5_d, 98 I2S2_MCLK_M1/SPI1_CLK_M0/RGMII_TXCLK_M0/VO_LCDC_D15/GPIO3_D6_d, 99 SPI1_CSN0_M0/UART8_CTSN_M1/RGMII_RXD2_M0/VO_LCDC_D19/GPIO3_D7_d, 100 SPI1_CSN1_M0/UART8_RTSN_M1/RGMII_RXD3_M0/VO_LCDC_D20/GPIO4_A0_d, 101 I2S2_LRCK_M1/PWM12_M0/RGMII_RXCLK_M0/VO_LCDC_D21/GPIO4_A1_d, 102 UART6_CTSN_M1/SPI1_MOSI_M0/RGMII_TXD0_M0/VO_LCDC_D22/GPIO4_A2_d, 103 UART6_RTSN_M1/SPI1_MISO_M0/RGMII_TXD1_M0/VO_LCDC_D23/GPIO4_A3_d, 104 PWM13_M0/RGMII_TXEN_M0/VO_LCDC_D0/GPIO4_A4_d, 105 I2C3_SCL_M1/PDM_SDI2_M1/UART1_TX_M1/RGMII_RXD0_M0/VO_LCDC_D1/GPIO4_A5_d, 106 I2C3_SDA_M1/PDM_SDI3_M1/UART1_RX_M1/RGMII_RXD1_M0/VO_LCDC_D8/GPIO4_A6_d, 107 UART6_TX_M1/PDM_SDI0_M1/UART1_RTSN_M1/RGMII_RXDV_M0/VO_LCDC_D9/GPIO4_A7_d, 108 UART6_RX_M1/PDM_SDI1_M1/UART1_CTSN_M1/RGMII_RXER_M0/VO_LCDC_D16/GPIO4_B0_d, 109 I2S2_SCLK_M1/CAM_CLK0_OUT_M1/PDM_CLK1_M1/ETH_CLK_25M_OUT_M0/VO_LCDC_D17/GPIO4_B1_d, 110 UART9_TX_M0/RGMII_MDC_M0/VO_LCDC_D2/GPIO4_B2_d, 111 UART9_RX_M0/RGMII_MDIO_M0/VO_LCDC_D18/GPIO4_B3_d, 112 UART3_TX_M0/I2C1_SCL_M1/SPI2_CSN1_M0/UART9_CTSN_M0/I2S1_SDO1_M0/VO_LCDC_HSYNC/GPIO4_B4_d, 113 UART3_RX_M0/I2C1_SDA_M1/SPI2_CSN0_M0/UART9_RTSN_M0/I2S1_SDO2_M0/VO_LCDC_VSYNC/GPIO4_B5_d, 114 UART3_CTSN_M0/SPI2_CLK_M0/I2S1_SDO3_M0/VO_LCDC_DEN/GPIO4_B6_d, 115 CAM_CLK1_OUT_M1/PDM_CLK0_M1/RGMII_CLK_M0/VO_LCDC_CLK/GPIO4_B7_d, 116 VCCIO6_IN, 117 GND117, 118 MIPI_CSI_RX1_CLK1P, 119 MIPI_CSI_RX1_CLK1N, 120 MIPI_CSI_RX1_D3P, 121 MIPI_CSI_RX1_D3N, 122 MIPI_CSI_RX1_D2P, 123 MIPI_CSI_RX1_D2N, 124 MIPI_CSI_RX1_CLK0P, 125 MIPI_CSI_RX1_CLK0N, 126 MIPI_CSI_RX1_D1P, 127 MIPI_CSI_RX1_D1N, 128 MIPI_CSI_RX1_D0P, 129 MIPI_CSI_RX1_D0N, 130 MIPI_CSI_RX0_CLK1P, 131 MIPI_CSI_RX0_CLK1N, 132 MIPI_CSI_RX0_D3P, 133 MIPI_CSI_RX0_D3N, 134 MIPI_CSI_RX0_D2P, 135 MIPI_CSI_RX0_D2N, 136 MIPI_CSI_RX0_CLK0P, 137 MIPI_CSI_RX0_CLK0N, 138 MIPI_CSI_RX0_D1P, 139 MIPI_CSI_RX0_D1N, 140 MIPI_CSI_RX0_D0P, 141 MIPI_CSI_RX0_D0N, 142 MIPI_DSI_TX_D3P/LVDS_TX_D3P, 143 MIPI_DSI_TX_D3N/LVDS_TX_D3N, 144 MIPI_DSI_TX_D2P/LVDS_TX_D2P, 145 MIPI_DSI_TX_D2N/LVDS_TX_D2N, 146 MIPI_DSI_TX_CLKP/LVDS_TX_CLKP, 147 MIPI_DSI_TX_CLKN/LVDS_TX_CLKN, 148 MIPI_DSI_TX_D1P/LVDS_TX_D1P, 149 MIPI_DSI_TX_D1N/LVDS_TX_D1N, 150 MIPI_DSI_TX_D0P/LVDS_TX_D0P, 151 MIPI_DSI_TX_D0N/LVDS_TX_D0N, 152 GND152, 153 I2C1_SCL_M0/GPIO0_B3_d, 154 I2C1_SDA_M0/GPIO0_B4_d, 155 PCIE20_PERSTN_M0/I2C2_SCL_M0/GPIO0_B5_d, 156 PCIE20_WAKEN_M0/I2C2_SDA_M0/GPIO0_B6_d, 157 SPDIF_TX_M1/CPU_AVS/PWM4_M0/SPI0_CSN1_M0/GPIO0_B7_d, 158 GPU_AVS/PWM7_M0/UART2_TX_M0/GPIO0_C0_d, 159 SPI0_CSN0_M0/PWM5_M0/UART2_CTSN_M0/GPIO0_C2_d, 160 SPI0_CLK_M0/PWM0_M0/UART2_RTSN_M0/GPIO0_C3_d, 161 SPI0_MOSI_M0/PWM1_M0/UART6_CTSN_M0/GPIO0_C4_d, 162 SPI0_MISO_M0/PWM2_M0/UART6_RTSN_M0/GPIO0_C5_d, 163 UART6_TX_M0/GPIO0_C6_d, 164 UART6_RX_M0/GPIO0_C7_d, 165 JTAG_CPU_MCU_TMS_M0/UART0_RX_M0/GPIO0_D0_u, 166 JTAG_CPU_MCU_TCK_M0/UART0_TX_M0/GPIO0_D1_u, 167 PCIE20_BUTTONRSTN/CLK0_32K_OUT/CLK_32K_IN/GPIO0_B0_d, 168 PWM3_M0/GPIO0_A7_d, 169 PCIE20_CLKREQN_M0/GPIO0_A6_d, 170 PMU_DEBUG/I2C4_SCL_M1/SDMMC0_PWREN/GPIO0_A5_d, 171 I2C4_SDA_M1/SDMMC0_DETN/GPIO0_A4_u, 172 REF_CLK_OUT/GPIO0_A0_d, 173 GND173, 174 SPKP_OUT, 175 SPKN_OUT, 176 BATDIV, 177 SNSP, 178 SNSN, 179 SARADC0_BOOT, 180 GND180, 181 GND181, 182 GND182

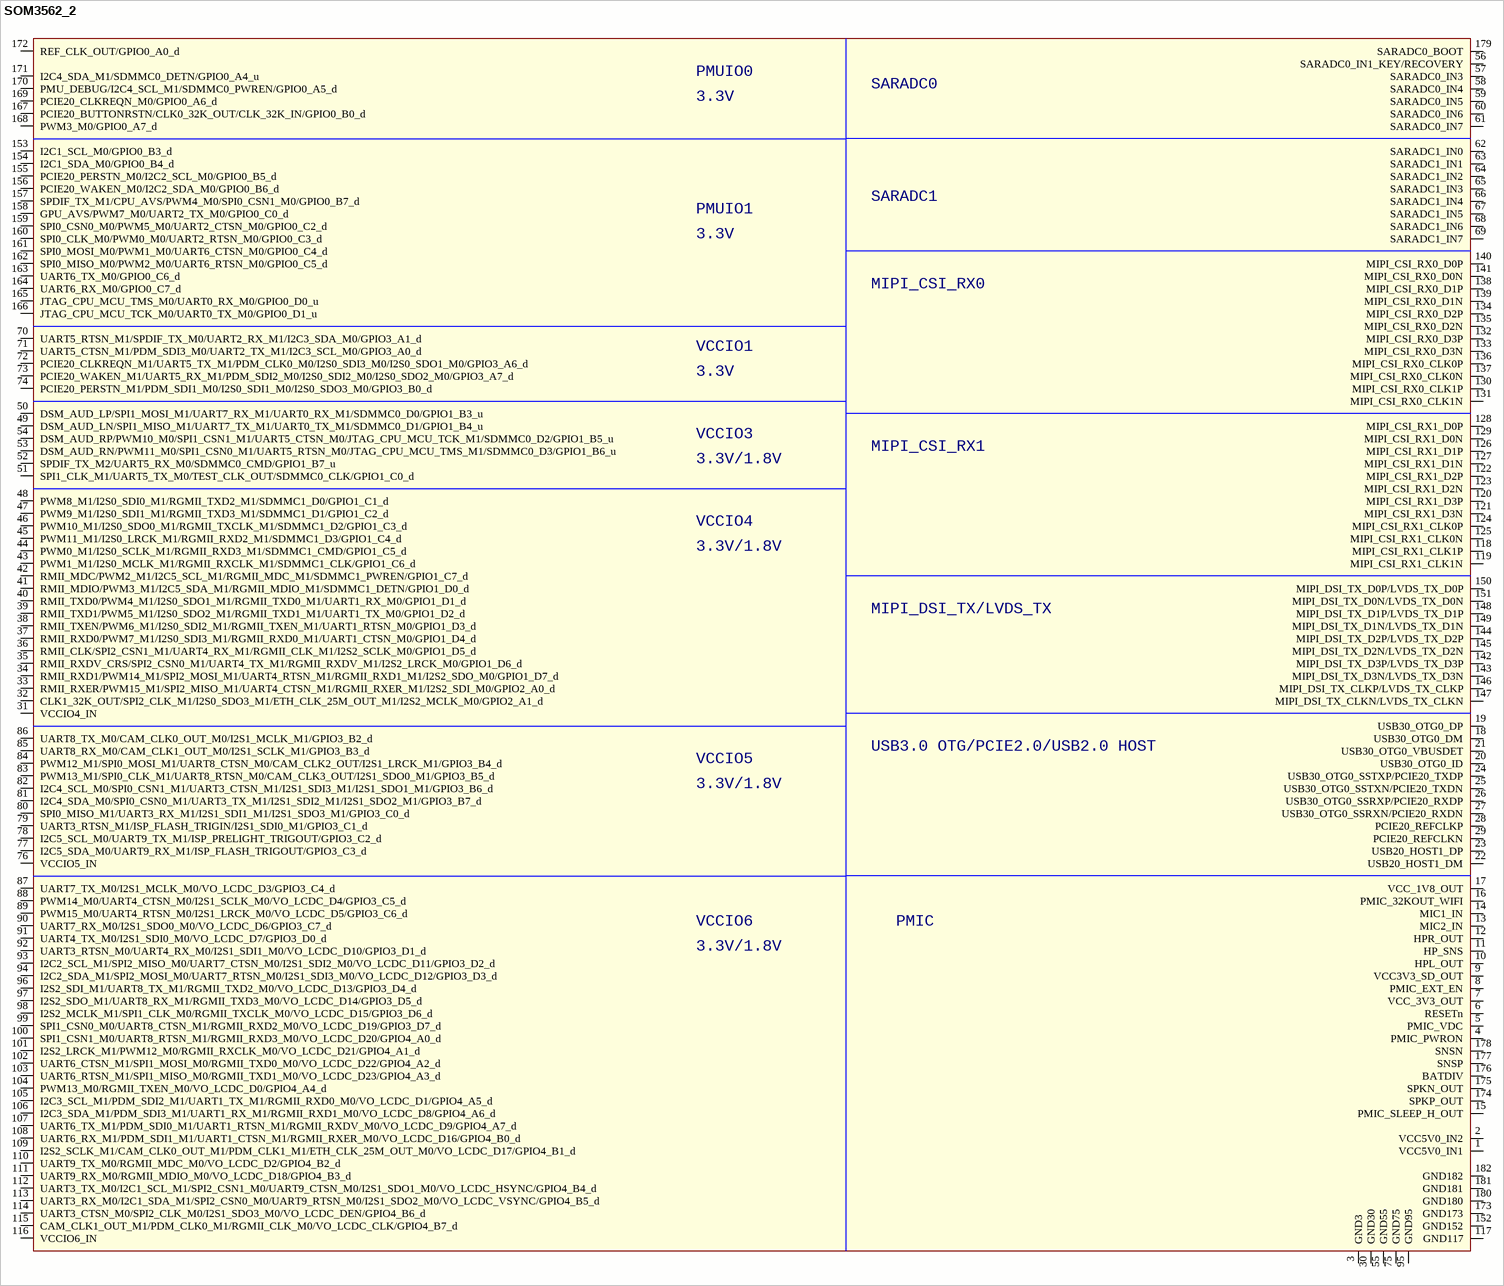
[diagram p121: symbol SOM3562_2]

## SOM3562_2
designator M?
Altium-Right: 1150; Altium-Bottom: 970
footprint SOM3562-182P
pins: 1 VCC5V0_IN1, 2 VCC5V0_IN2, 3 GND3, 4 PMIC_PWRON, 5 PMIC_VDC, 6 RESETn, 7 VCC_3V3_OUT, 8 PMIC_EXT_EN, 9 VCC3V3_SD_OUT, 10 HPL_OUT, 11 HP_SNS, 12 HPR_OUT, 13 MIC2_IN, 14 MIC1_IN, 15 PMIC_SLEEP_H_OUT, 16 PMIC_32KOUT_WIFI, 17 VCC_1V8_OUT, 18 USB30_OTG0_DM, 19 USB30_OTG0_DP, 20 USB30_OTG0_ID, 21 USB30_OTG0_VBUSDET, 22 USB20_HOST1_DM, 23 USB20_HOST1_DP, 24 USB30_OTG0_SSTXP/PCIE20_TXDP, 25 USB30_OTG0_SSTXN/PCIE20_TXDN, 26 USB30_OTG0_SSRXP/PCIE20_RXDP, 27 USB30_OTG0_SSRXN/PCIE20_RXDN, 28 PCIE20_REFCLKP, 29 PCIE20_REFCLKN, 30 GND30, 31 VCCIO4_IN, 32 CLK1_32K_OUT/SPI2_CLK_M1/I2S0_SDO3_M1/ETH_CLK_25M_OUT_M1/I2S2_MCLK_M0/GPIO2_A1_d, 33 RMII_RXER/PWM15_M1/SPI2_MISO_M1/UART4_CTSN_M1/RGMII_RXER_M1/I2S2_SDI_M0/GPIO2_A0_d, 34 RMII_RXD1/PWM14_M1/SPI2_MOSI_M1/UART4_RTSN_M1/RGMII_RXD1_M1/I2S2_SDO_M0/GPIO1_D7_d, 35 RMII_RXDV_CRS/SPI2_CSN0_M1/UART4_TX_M1/RGMII_RXDV_M1/I2S2_LRCK_M0/GPIO1_D6_d, 36 RMII_CLK/SPI2_CSN1_M1/UART4_RX_M1/RGMII_CLK_M1/I2S2_SCLK_M0/GPIO1_D5_d, 37 RMII_RXD0/PWM7_M1/I2S0_SDI3_M1/RGMII_RXD0_M1/UART1_CTSN_M0/GPIO1_D4_d, 38 RMII_TXEN/PWM6_M1/I2S0_SDI2_M1/RGMII_TXEN_M1/UART1_RTSN_M0/GPIO1_D3_d, 39 RMII_TXD1/PWM5_M1/I2S0_SDO2_M1/RGMII_TXD1_M1/UART1_TX_M0/GPIO1_D2_d, 40 RMII_TXD0/PWM4_M1/I2S0_SDO1_M1/RGMII_TXD0_M1/UART1_RX_M0/GPIO1_D1_d, 41 RMII_MDIO/PWM3_M1/I2C5_SDA_M1/RGMII_MDIO_M1/SDMMC1_DETN/GPIO1_D0_d, 42 RMII_MDC/PWM2_M1/I2C5_SCL_M1/RGMII_MDC_M1/SDMMC1_PWREN/GPIO1_C7_d, 43 PWM1_M1/I2S0_MCLK_M1/RGMII_RXCLK_M1/SDMMC1_CLK/GPIO1_C6_d, 44 PWM0_M1/I2S0_SCLK_M1/RGMII_RXD3_M1/SDMMC1_CMD/GPIO1_C5_d, 45 PWM11_M1/I2S0_LRCK_M1/RGMII_RXD2_M1/SDMMC1_D3/GPIO1_C4_d, 46 PWM10_M1/I2S0_SDO0_M1/RGMII_TXCLK_M1/SDMMC1_D2/GPIO1_C3_d, 47 PWM9_M1/I2S0_SDI1_M1/RGMII_TXD3_M1/SDMMC1_D1/GPIO1_C2_d, 48 PWM8_M1/I2S0_SDI0_M1/RGMII_TXD2_M1/SDMMC1_D0/GPIO1_C1_d, 49 DSM_AUD_LN/SPI1_MISO_M1/UART7_TX_M1/UART0_TX_M1/SDMMC0_D1/GPIO1_B4_u, 50 DSM_AUD_LP/SPI1_MOSI_M1/UART7_RX_M1/UART0_RX_M1/SDMMC0_D0/GPIO1_B3_u, 51 SPI1_CLK_M1/UART5_TX_M0/TEST_CLK_OUT/SDMMC0_CLK/GPIO1_C0_d, 52 SPDIF_TX_M2/UART5_RX_M0/SDMMC0_CMD/GPIO1_B7_u, 53 DSM_AUD_RN/PWM11_M0/SPI1_CSN0_M1/UART5_RTSN_M0/JTAG_CPU_MCU_TMS_M1/SDMMC0_D3/GPIO1_B6_u, 54 DSM_AUD_RP/PWM10_M0/SPI1_CSN1_M1/UART5_CTSN_M0/JTAG_CPU_MCU_TCK_M1/SDMMC0_D2/GPIO1_B5_u, 55 GND55, 56 SARADC0_IN1_KEY/RECOVERY, 57 SARADC0_IN3, 58 SARADC0_IN4, 59 SARADC0_IN5, 60 SARADC0_IN6, 61 SARADC0_IN7, 62 SARADC1_IN0, 63 SARADC1_IN1, 64 SARADC1_IN2, 65 SARADC1_IN3, 66 SARADC1_IN4, 67 SARADC1_IN5, 68 SARADC1_IN6, 69 SARADC1_IN7, 70 UART5_RTSN_M1/SPDIF_TX_M0/UART2_RX_M1/I2C3_SDA_M0/GPIO3_A1_d, 71 UART5_CTSN_M1/PDM_SDI3_M0/UART2_TX_M1/I2C3_SCL_M0/GPIO3_A0_d, 72 PCIE20_CLKREQN_M1/UART5_TX_M1/PDM_CLK0_M0/I2S0_SDI3_M0/I2S0_SDO1_M0/GPIO3_A6_d, 73 PCIE20_WAKEN_M1/UART5_RX_M1/PDM_SDI2_M0/I2S0_SDI2_M0/I2S0_SDO2_M0/GPIO3_A7_d, 74 PCIE20_PERSTN_M1/PDM_SDI1_M0/I2S0_SDI1_M0/I2S0_SDO3_M0/GPIO3_B0_d, 75 GND75, 76 VCCIO5_IN, 77 I2C5_SDA_M0/UART9_RX_M1/ISP_FLASH_TRIGOUT/GPIO3_C3_d, 78 I2C5_SCL_M0/UART9_TX_M1/ISP_PRELIGHT_TRIGOUT/GPIO3_C2_d, 79 UART3_RTSN_M1/ISP_FLASH_TRIGIN/I2S1_SDI0_M1/GPIO3_C1_d, 80 SPI0_MISO_M1/UART3_RX_M1/I2S1_SDI1_M1/I2S1_SDO3_M1/GPIO3_C0_d, 81 I2C4_SDA_M0/SPI0_CSN0_M1/UART3_TX_M1/I2S1_SDI2_M1/I2S1_SDO2_M1/GPIO3_B7_d, 82 I2C4_SCL_M0/SPI0_CSN1_M1/UART3_CTSN_M1/I2S1_SDI3_M1/I2S1_SDO1_M1/GPIO3_B6_d, 83 PWM13_M1/SPI0_CLK_M1/UART8_RTSN_M0/CAM_CLK3_OUT/I2S1_SDO0_M1/GPIO3_B5_d, 84 PWM12_M1/SPI0_MOSI_M1/UART8_CTSN_M0/CAM_CLK2_OUT/I2S1_LRCK_M1/GPIO3_B4_d, 85 UART8_RX_M0/CAM_CLK1_OUT_M0/I2S1_SCLK_M1/GPIO3_B3_d, 86 UART8_TX_M0/CAM_CLK0_OUT_M0/I2S1_MCLK_M1/GPIO3_B2_d, 87 UART7_TX_M0/I2S1_MCLK_M0/VO_LCDC_D3/GPIO3_C4_d, 88 PWM14_M0/UART4_CTSN_M0/I2S1_SCLK_M0/VO_LCDC_D4/GPIO3_C5_d, 89 PWM15_M0/UART4_RTSN_M0/I2S1_LRCK_M0/VO_LCDC_D5/GPIO3_C6_d, 90 UART7_RX_M0/I2S1_SDO0_M0/VO_LCDC_D6/GPIO3_C7_d, 91 UART4_TX_M0/I2S1_SDI0_M0/VO_LCDC_D7/GPIO3_D0_d, 92 UART3_RTSN_M0/UART4_RX_M0/I2S1_SDI1_M0/VO_LCDC_D10/GPIO3_D1_d, 93 I2C2_SCL_M1/SPI2_MISO_M0/UART7_CTSN_M0/I2S1_SDI2_M0/VO_LCDC_D11/GPIO3_D2_d, 94 I2C2_SDA_M1/SPI2_MOSI_M0/UART7_RTSN_M0/I2S1_SDI3_M0/VO_LCDC_D12/GPIO3_D3_d, 95 GND95, 96 I2S2_SDI_M1/UART8_TX_M1/RGMII_TXD2_M0/VO_LCDC_D13/GPIO3_D4_d, 97 I2S2_SDO_M1/UART8_RX_M1/RGMII_TXD3_M0/VO_LCDC_D14/GPIO3_D5_d, 98 I2S2_MCLK_M1/SPI1_CLK_M0/RGMII_TXCLK_M0/VO_LCDC_D15/GPIO3_D6_d, 99 SPI1_CSN0_M0/UART8_CTSN_M1/RGMII_RXD2_M0/VO_LCDC_D19/GPIO3_D7_d, 100 SPI1_CSN1_M0/UART8_RTSN_M1/RGMII_RXD3_M0/VO_LCDC_D20/GPIO4_A0_d, 101 I2S2_LRCK_M1/PWM12_M0/RGMII_RXCLK_M0/VO_LCDC_D21/GPIO4_A1_d, 102 UART6_CTSN_M1/SPI1_MOSI_M0/RGMII_TXD0_M0/VO_LCDC_D22/GPIO4_A2_d, 103 UART6_RTSN_M1/SPI1_MISO_M0/RGMII_TXD1_M0/VO_LCDC_D23/GPIO4_A3_d, 104 PWM13_M0/RGMII_TXEN_M0/VO_LCDC_D0/GPIO4_A4_d, 105 I2C3_SCL_M1/PDM_SDI2_M1/UART1_TX_M1/RGMII_RXD0_M0/VO_LCDC_D1/GPIO4_A5_d, 106 I2C3_SDA_M1/PDM_SDI3_M1/UART1_RX_M1/RGMII_RXD1_M0/VO_LCDC_D8/GPIO4_A6_d, 107 UART6_TX_M1/PDM_SDI0_M1/UART1_RTSN_M1/RGMII_RXDV_M0/VO_LCDC_D9/GPIO4_A7_d, 108 UART6_RX_M1/PDM_SDI1_M1/UART1_CTSN_M1/RGMII_RXER_M0/VO_LCDC_D16/GPIO4_B0_d, 109 I2S2_SCLK_M1/CAM_CLK0_OUT_M1/PDM_CLK1_M1/ETH_CLK_25M_OUT_M0/VO_LCDC_D17/GPIO4_B1_d, 110 UART9_TX_M0/RGMII_MDC_M0/VO_LCDC_D2/GPIO4_B2_d, 111 UART9_RX_M0/RGMII_MDIO_M0/VO_LCDC_D18/GPIO4_B3_d, 112 UART3_TX_M0/I2C1_SCL_M1/SPI2_CSN1_M0/UART9_CTSN_M0/I2S1_SDO1_M0/VO_LCDC_HSYNC/GPIO4_B4_d, 113 UART3_RX_M0/I2C1_SDA_M1/SPI2_CSN0_M0/UART9_RTSN_M0/I2S1_SDO2_M0/VO_LCDC_VSYNC/GPIO4_B5_d, 114 UART3_CTSN_M0/SPI2_CLK_M0/I2S1_SDO3_M0/VO_LCDC_DEN/GPIO4_B6_d, 115 CAM_CLK1_OUT_M1/PDM_CLK0_M1/RGMII_CLK_M0/VO_LCDC_CLK/GPIO4_B7_d, 116 VCCIO6_IN, 117 GND117, 118 MIPI_CSI_RX1_CLK1P, 119 MIPI_CSI_RX1_CLK1N, 120 MIPI_CSI_RX1_D3P, 121 MIPI_CSI_RX1_D3N, 122 MIPI_CSI_RX1_D2P, 123 MIPI_CSI_RX1_D2N, 124 MIPI_CSI_RX1_CLK0P, 125 MIPI_CSI_RX1_CLK0N, 126 MIPI_CSI_RX1_D1P, 127 MIPI_CSI_RX1_D1N, 128 MIPI_CSI_RX1_D0P, 129 MIPI_CSI_RX1_D0N, 130 MIPI_CSI_RX0_CLK1P, 131 MIPI_CSI_RX0_CLK1N, 132 MIPI_CSI_RX0_D3P, 133 MIPI_CSI_RX0_D3N, 134 MIPI_CSI_RX0_D2P, 135 MIPI_CSI_RX0_D2N, 136 MIPI_CSI_RX0_CLK0P, 137 MIPI_CSI_RX0_CLK0N, 138 MIPI_CSI_RX0_D1P, 139 MIPI_CSI_RX0_D1N, 140 MIPI_CSI_RX0_D0P, 141 MIPI_CSI_RX0_D0N, 142 MIPI_DSI_TX_D3P/LVDS_TX_D3P, 143 MIPI_DSI_TX_D3N/LVDS_TX_D3N, 144 MIPI_DSI_TX_D2P/LVDS_TX_D2P, 145 MIPI_DSI_TX_D2N/LVDS_TX_D2N, 146 MIPI_DSI_TX_CLKP/LVDS_TX_CLKP, 147 MIPI_DSI_TX_CLKN/LVDS_TX_CLKN, 148 MIPI_DSI_TX_D1P/LVDS_TX_D1P, 149 MIPI_DSI_TX_D1N/LVDS_TX_D1N, 150 MIPI_DSI_TX_D0P/LVDS_TX_D0P, 151 MIPI_DSI_TX_D0N/LVDS_TX_D0N, 152 GND152, 153 I2C1_SCL_M0/GPIO0_B3_d, 154 I2C1_SDA_M0/GPIO0_B4_d, 155 PCIE20_PERSTN_M0/I2C2_SCL_M0/GPIO0_B5_d, 156 PCIE20_WAKEN_M0/I2C2_SDA_M0/GPIO0_B6_d, 157 SPDIF_TX_M1/CPU_AVS/PWM4_M0/SPI0_CSN1_M0/GPIO0_B7_d, 158 GPU_AVS/PWM7_M0/UART2_TX_M0/GPIO0_C0_d, 159 SPI0_CSN0_M0/PWM5_M0/UART2_CTSN_M0/GPIO0_C2_d, 160 SPI0_CLK_M0/PWM0_M0/UART2_RTSN_M0/GPIO0_C3_d, 161 SPI0_MOSI_M0/PWM1_M0/UART6_CTSN_M0/GPIO0_C4_d, 162 SPI0_MISO_M0/PWM2_M0/UART6_RTSN_M0/GPIO0_C5_d, 163 UART6_TX_M0/GPIO0_C6_d, 164 UART6_RX_M0/GPIO0_C7_d, 165 JTAG_CPU_MCU_TMS_M0/UART0_RX_M0/GPIO0_D0_u, 166 JTAG_CPU_MCU_TCK_M0/UART0_TX_M0/GPIO0_D1_u, 167 PCIE20_BUTTONRSTN/CLK0_32K_OUT/CLK_32K_IN/GPIO0_B0_d, 168 PWM3_M0/GPIO0_A7_d, 169 PCIE20_CLKREQN_M0/GPIO0_A6_d, 170 PMU_DEBUG/I2C4_SCL_M1/SDMMC0_PWREN/GPIO0_A5_d, 171 I2C4_SDA_M1/SDMMC0_DETN/GPIO0_A4_u, 172 REF_CLK_OUT/GPIO0_A0_d, 173 GND173, 174 SPKP_OUT, 175 SPKN_OUT, 176 BATDIV, 177 SNSP, 178 SNSN, 179 SARADC0_BOOT, 180 GND180, 181 GND181, 182 GND182

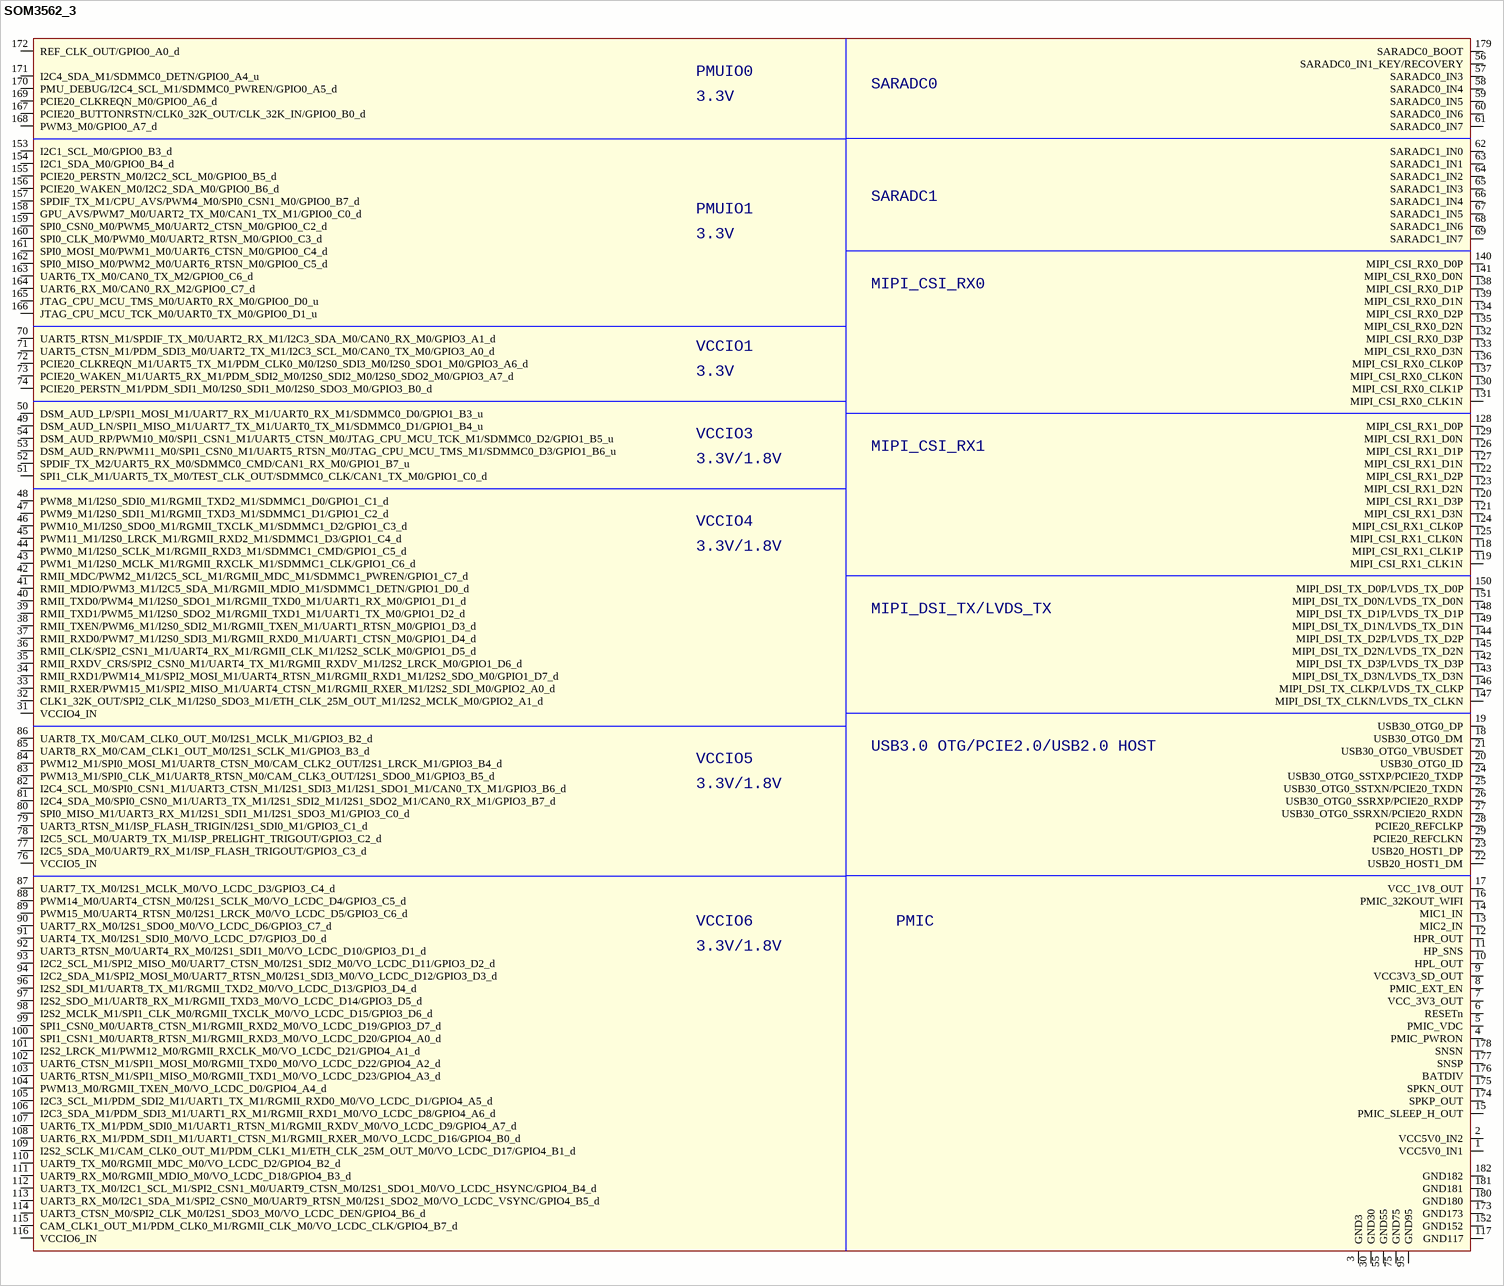
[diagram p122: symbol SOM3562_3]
